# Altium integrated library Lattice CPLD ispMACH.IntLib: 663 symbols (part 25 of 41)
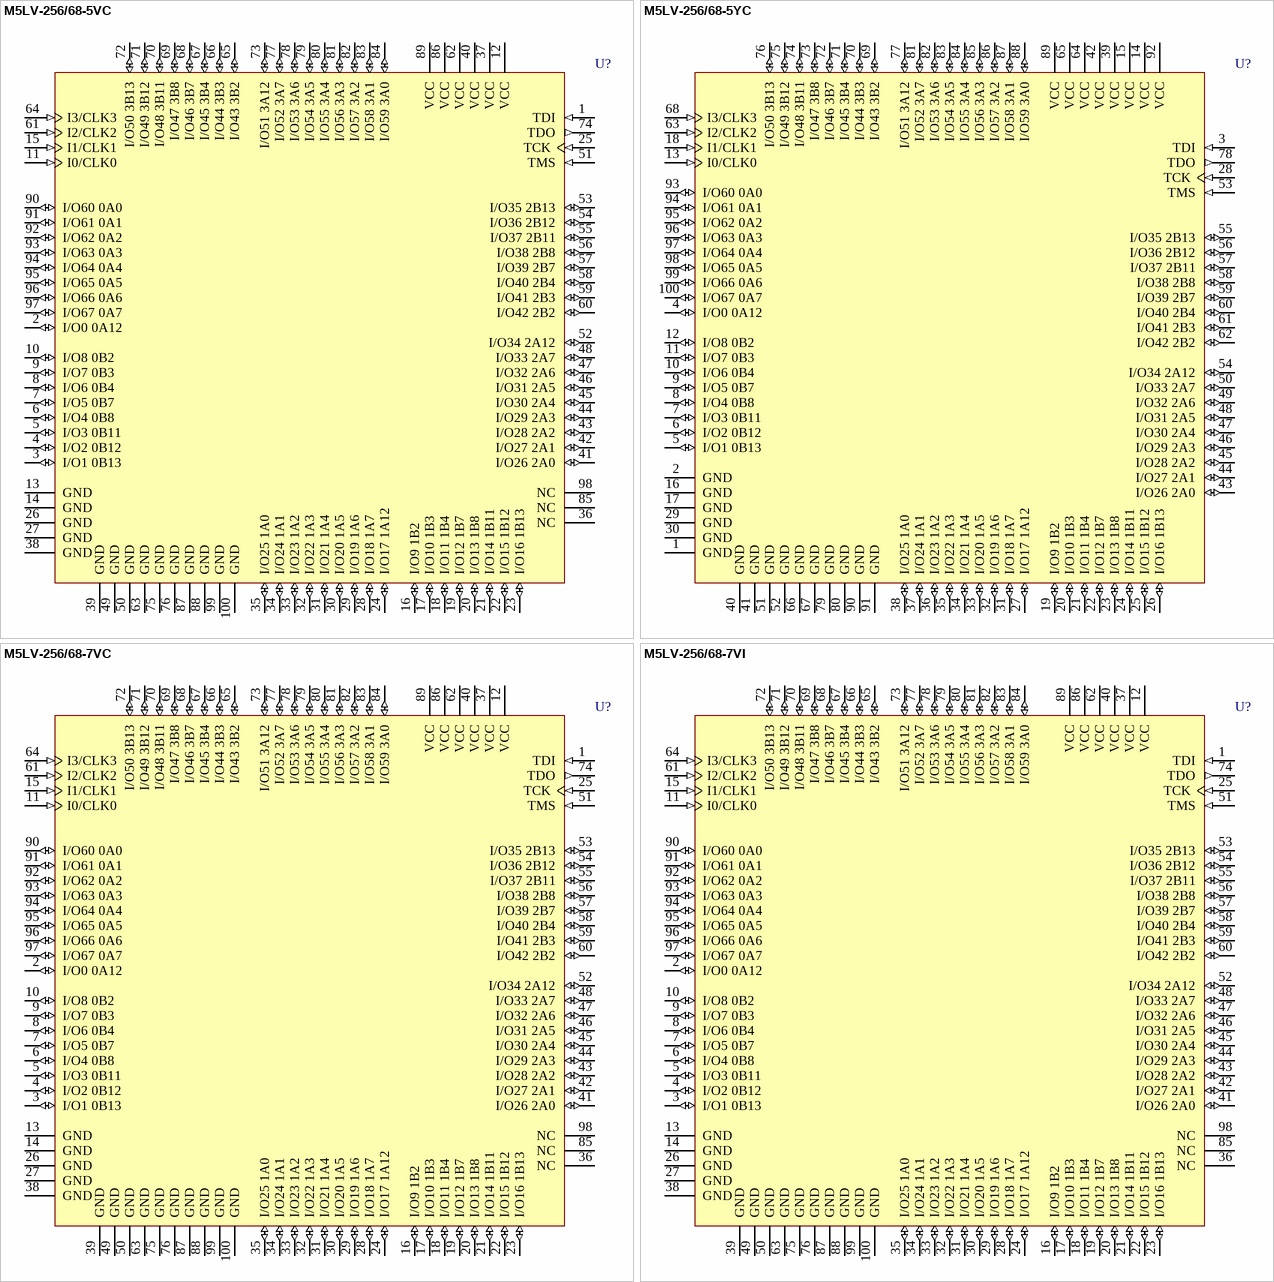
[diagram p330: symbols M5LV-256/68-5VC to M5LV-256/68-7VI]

## M5LV-256/68-7VI
designator U?
High-Density and High-I/O Complex PLD
footprint TQFP100_N (Thin QFP, 100-Leads, Body 14x14mm, Pitch 0.5mm, IPC Medium Density)
footprint TQFP100_L (Thin QFP, 100-Leads, Body 14x14mm, Pitch 0.5mm, IPC High Density)
footprint TQFP100_M (Thin QFP, 100-Leads, Body 14x14mm, Pitch 0.5mm, IPC Low Density)
3D model M5LV-TQFP100 (100-Pin Thin Quad Flat Pack (TQFP100))
pins: 1 TDI (in), 2 I/O0 0A12 (io), 3 I/O1 0B13 (io), 4 I/O2 0B12 (io), 5 I/O3 0B11 (io), 6 I/O4 0B8 (io), 7 I/O5 0B7 (io), 8 I/O6 0B4 (io), 9 I/O7 0B3 (io), 10 I/O8 0B2 (io), 11 I0/CLK0 (in), 12 VCC (power), 13 GND (power), 14 GND (power), 15 I1/CLK1 (in), 16 I/O9 1B2 (io), 17 I/O10 1B3 (io), 18 I/O11 1B4 (io), 19 I/O12 1B7 (io), 20 I/O13 1B8 (io), 21 I/O14 1B11 (io), 22 I/O15 1B12 (io), 23 I/O16 1B13 (io), 24 I/O17 1A12 (io), 25 TCK (in), 26 GND (power), 27 GND (power), 28 I/O18 1A7 (io), 29 I/O19 1A6 (io), 30 I/O20 1A5 (io), 31 I/O21 1A4 (io), 32 I/O22 1A3 (io), 33 I/O23 1A2 (io), 34 I/O24 1A1 (io), 35 I/O25 1A0 (io), 36 NC, 37 VCC (power), 38 GND (power), 39 GND (power), 40 VCC (power), 41 I/O26 2A0 (io), 42 I/O27 2A1 (io), 43 I/O28 2A2 (io), 44 I/O29 2A3 (io), 45 I/O30 2A4 (io), 46 I/O31 2A5 (io), 47 I/O32 2A6 (io), 48 I/O33 2A7 (io), 49 GND (power), 50 GND (power), 51 TMS (in), 52 I/O34 2A12 (io), 53 I/O35 2B13 (io), 54 I/O36 2B12 (io), 55 I/O37 2B11 (io), 56 I/O38 2B8 (io), 57 I/O39 2B7 (io), 58 I/O40 2B4 (io), 59 I/O41 2B3 (io), 60 I/O42 2B2 (io), 61 I2/CLK2 (in), 62 VCC (power), 63 GND (power), 64 I3/CLK3 (in), 65 I/O43 3B2 (io), 66 I/O44 3B3 (io), 67 I/O45 3B4 (io), 68 I/O46 3B7 (io), 69 I/O47 3B8 (io), 70 I/O48 3B11 (io), 71 I/O49 3B12 (io), 72 I/O50 3B13 (io), 73 I/O51 3A12 (io), 74 TDO (out), 75 GND (power), 76 GND (power), 77 I/O52 3A7 (io), 78 I/O53 3A6 (io), 79 I/O54 3A5 (io), 80 I/O55 3A4 (io), 81 I/O56 3A3 (io), 82 I/O57 3A2 (io), 83 I/O58 3A1 (io), 84 I/O59 3A0 (io), 85 NC, 86 VCC (power), 87 GND (power), 88 GND (power), 89 VCC (power), 90 I/O60 0A0 (io), 91 I/O61 0A1 (io), 92 I/O62 0A2 (io), 93 I/O63 0A3 (io), 94 I/O64 0A4 (io), 95 I/O65 0A5 (io), 96 I/O66 0A6 (io), 97 I/O67 0A7 (io), 98 NC, 99 GND (power), 100 GND (power)

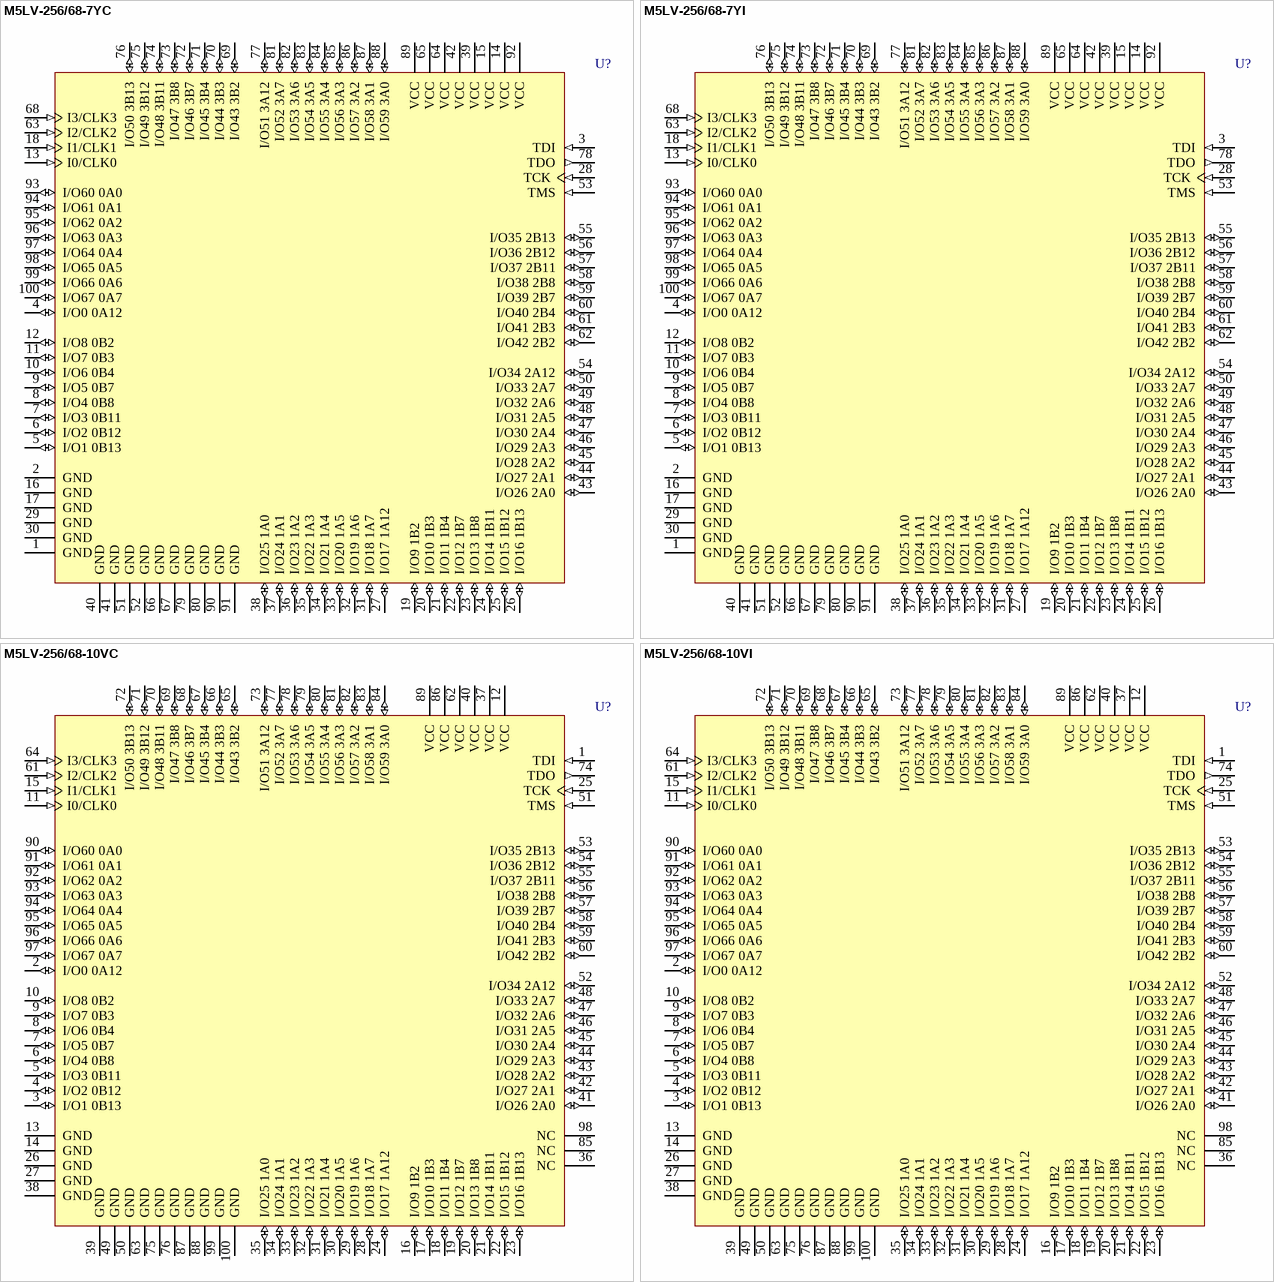
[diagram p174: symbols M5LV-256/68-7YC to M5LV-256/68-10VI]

## M5LV-256/68-7YC
designator U?
High-Density and High-I/O Complex PLD
footprint PQFP100_N (QFP, 100-Leads, Body 20x14mm, Pitch 0.65mm, IPC Medium Density)
footprint PQFP100_L (QFP, 100-Leads, Body 20x14mm, Pitch 0.65mm, IPC High Density)
footprint PQFP100_M (QFP, 100-Leads, Body 20x14mm, Pitch 0.65mm, IPC Low Density)
3D model PQFP-100 (100-Pin Quad Flat Pack Rectangular 0.65 mm Pitch)
pins: 1 GND (power), 2 GND (power), 3 TDI (in), 4 I/O0 0A12 (io), 5 I/O1 0B13 (io), 6 I/O2 0B12 (io), 7 I/O3 0B11 (io), 8 I/O4 0B8 (io), 9 I/O5 0B7 (io), 10 I/O6 0B4 (io), 11 I/O7 0B3 (io), 12 I/O8 0B2 (io), 13 I0/CLK0 (in), 14 VCC (power), 15 VCC (power), 16 GND (power), 17 GND (power), 18 I1/CLK1 (in), 19 I/O9 1B2 (io), 20 I/O10 1B3 (io), 21 I/O11 1B4 (io), 22 I/O12 1B7 (io), 23 I/O13 1B8 (io), 24 I/O14 1B11 (io), 25 I/O15 1B12 (io), 26 I/O16 1B13 (io), 27 I/O17 1A12 (io), 28 TCK (in), 29 GND (power), 30 GND (power), 31 I/O18 1A7 (io), 32 I/O19 1A6 (io), 33 I/O20 1A5 (io), 34 I/O21 1A4 (io), 35 I/O22 1A3 (io), 36 I/O23 1A2 (io), 37 I/O24 1A1 (io), 38 I/O25 1A0 (io), 39 VCC (power), 40 GND (power), 41 GND (power), 42 VCC (power), 43 I/O26 2A0 (io), 44 I/O27 2A1 (io), 45 I/O28 2A2 (io), 46 I/O29 2A3 (io), 47 I/O30 2A4 (io), 48 I/O31 2A5 (io), 49 I/O32 2A6 (io), 50 I/O33 2A7 (io), 51 GND (power), 52 GND (power), 53 TMS (in), 54 I/O34 2A12 (io), 55 I/O35 2B13 (io), 56 I/O36 2B12 (io), 57 I/O37 2B11 (io), 58 I/O38 2B8 (io), 59 I/O39 2B7 (io), 60 I/O40 2B4 (io), 61 I/O41 2B3 (io), 62 I/O42 2B2 (io), 63 I2/CLK2 (in), 64 VCC (power), 65 VCC (power), 66 GND (power), 67 GND (power), 68 I3/CLK3 (in), 69 I/O43 3B2 (io), 70 I/O44 3B3 (io), 71 I/O45 3B4 (io), 72 I/O46 3B7 (io), 73 I/O47 3B8 (io), 74 I/O48 3B11 (io), 75 I/O49 3B12 (io), 76 I/O50 3B13 (io), 77 I/O51 3A12 (io), 78 TDO (out), 79 GND (power), 80 GND (power), 81 I/O52 3A7 (io), 82 I/O53 3A6 (io), 83 I/O54 3A5 (io), 84 I/O55 3A4 (io), 85 I/O56 3A3 (io), 86 I/O57 3A2 (io), 87 I/O58 3A1 (io), 88 I/O59 3A0 (io), 89 VCC (power), 90 GND (power), 91 GND (power), 92 VCC (power), 93 I/O60 0A0 (io), 94 I/O61 0A1 (io), 95 I/O62 0A2 (io), 96 I/O63 0A3 (io), 97 I/O64 0A4 (io), 98 I/O65 0A5 (io), 99 I/O66 0A6 (io), 100 I/O67 0A7 (io)

## M5LV-256/68-7YI
designator U?
High-Density and High-I/O Complex PLD
footprint PQFP100_N (QFP, 100-Leads, Body 20x14mm, Pitch 0.65mm, IPC Medium Density)
footprint PQFP100_L (QFP, 100-Leads, Body 20x14mm, Pitch 0.65mm, IPC High Density)
footprint PQFP100_M (QFP, 100-Leads, Body 20x14mm, Pitch 0.65mm, IPC Low Density)
3D model PQFP-100 (100-Pin Quad Flat Pack Rectangular 0.65 mm Pitch)
pins: 1 GND (power), 2 GND (power), 3 TDI (in), 4 I/O0 0A12 (io), 5 I/O1 0B13 (io), 6 I/O2 0B12 (io), 7 I/O3 0B11 (io), 8 I/O4 0B8 (io), 9 I/O5 0B7 (io), 10 I/O6 0B4 (io), 11 I/O7 0B3 (io), 12 I/O8 0B2 (io), 13 I0/CLK0 (in), 14 VCC (power), 15 VCC (power), 16 GND (power), 17 GND (power), 18 I1/CLK1 (in), 19 I/O9 1B2 (io), 20 I/O10 1B3 (io), 21 I/O11 1B4 (io), 22 I/O12 1B7 (io), 23 I/O13 1B8 (io), 24 I/O14 1B11 (io), 25 I/O15 1B12 (io), 26 I/O16 1B13 (io), 27 I/O17 1A12 (io), 28 TCK (in), 29 GND (power), 30 GND (power), 31 I/O18 1A7 (io), 32 I/O19 1A6 (io), 33 I/O20 1A5 (io), 34 I/O21 1A4 (io), 35 I/O22 1A3 (io), 36 I/O23 1A2 (io), 37 I/O24 1A1 (io), 38 I/O25 1A0 (io), 39 VCC (power), 40 GND (power), 41 GND (power), 42 VCC (power), 43 I/O26 2A0 (io), 44 I/O27 2A1 (io), 45 I/O28 2A2 (io), 46 I/O29 2A3 (io), 47 I/O30 2A4 (io), 48 I/O31 2A5 (io), 49 I/O32 2A6 (io), 50 I/O33 2A7 (io), 51 GND (power), 52 GND (power), 53 TMS (in), 54 I/O34 2A12 (io), 55 I/O35 2B13 (io), 56 I/O36 2B12 (io), 57 I/O37 2B11 (io), 58 I/O38 2B8 (io), 59 I/O39 2B7 (io), 60 I/O40 2B4 (io), 61 I/O41 2B3 (io), 62 I/O42 2B2 (io), 63 I2/CLK2 (in), 64 VCC (power), 65 VCC (power), 66 GND (power), 67 GND (power), 68 I3/CLK3 (in), 69 I/O43 3B2 (io), 70 I/O44 3B3 (io), 71 I/O45 3B4 (io), 72 I/O46 3B7 (io), 73 I/O47 3B8 (io), 74 I/O48 3B11 (io), 75 I/O49 3B12 (io), 76 I/O50 3B13 (io), 77 I/O51 3A12 (io), 78 TDO (out), 79 GND (power), 80 GND (power), 81 I/O52 3A7 (io), 82 I/O53 3A6 (io), 83 I/O54 3A5 (io), 84 I/O55 3A4 (io), 85 I/O56 3A3 (io), 86 I/O57 3A2 (io), 87 I/O58 3A1 (io), 88 I/O59 3A0 (io), 89 VCC (power), 90 GND (power), 91 GND (power), 92 VCC (power), 93 I/O60 0A0 (io), 94 I/O61 0A1 (io), 95 I/O62 0A2 (io), 96 I/O63 0A3 (io), 97 I/O64 0A4 (io), 98 I/O65 0A5 (io), 99 I/O66 0A6 (io), 100 I/O67 0A7 (io)

## M5LV-256/68-10VC
designator U?
High-Density and High-I/O Complex PLD
footprint TQFP100_N (Thin QFP, 100-Leads, Body 14x14mm, Pitch 0.5mm, IPC Medium Density)
footprint TQFP100_L (Thin QFP, 100-Leads, Body 14x14mm, Pitch 0.5mm, IPC High Density)
footprint TQFP100_M (Thin QFP, 100-Leads, Body 14x14mm, Pitch 0.5mm, IPC Low Density)
3D model M5LV-TQFP100 (100-Pin Thin Quad Flat Pack (TQFP100))
pins: 1 TDI (in), 2 I/O0 0A12 (io), 3 I/O1 0B13 (io), 4 I/O2 0B12 (io), 5 I/O3 0B11 (io), 6 I/O4 0B8 (io), 7 I/O5 0B7 (io), 8 I/O6 0B4 (io), 9 I/O7 0B3 (io), 10 I/O8 0B2 (io), 11 I0/CLK0 (in), 12 VCC (power), 13 GND (power), 14 GND (power), 15 I1/CLK1 (in), 16 I/O9 1B2 (io), 17 I/O10 1B3 (io), 18 I/O11 1B4 (io), 19 I/O12 1B7 (io), 20 I/O13 1B8 (io), 21 I/O14 1B11 (io), 22 I/O15 1B12 (io), 23 I/O16 1B13 (io), 24 I/O17 1A12 (io), 25 TCK (in), 26 GND (power), 27 GND (power), 28 I/O18 1A7 (io), 29 I/O19 1A6 (io), 30 I/O20 1A5 (io), 31 I/O21 1A4 (io), 32 I/O22 1A3 (io), 33 I/O23 1A2 (io), 34 I/O24 1A1 (io), 35 I/O25 1A0 (io), 36 NC, 37 VCC (power), 38 GND (power), 39 GND (power), 40 VCC (power), 41 I/O26 2A0 (io), 42 I/O27 2A1 (io), 43 I/O28 2A2 (io), 44 I/O29 2A3 (io), 45 I/O30 2A4 (io), 46 I/O31 2A5 (io), 47 I/O32 2A6 (io), 48 I/O33 2A7 (io), 49 GND (power), 50 GND (power), 51 TMS (in), 52 I/O34 2A12 (io), 53 I/O35 2B13 (io), 54 I/O36 2B12 (io), 55 I/O37 2B11 (io), 56 I/O38 2B8 (io), 57 I/O39 2B7 (io), 58 I/O40 2B4 (io), 59 I/O41 2B3 (io), 60 I/O42 2B2 (io), 61 I2/CLK2 (in), 62 VCC (power), 63 GND (power), 64 I3/CLK3 (in), 65 I/O43 3B2 (io), 66 I/O44 3B3 (io), 67 I/O45 3B4 (io), 68 I/O46 3B7 (io), 69 I/O47 3B8 (io), 70 I/O48 3B11 (io), 71 I/O49 3B12 (io), 72 I/O50 3B13 (io), 73 I/O51 3A12 (io), 74 TDO (out), 75 GND (power), 76 GND (power), 77 I/O52 3A7 (io), 78 I/O53 3A6 (io), 79 I/O54 3A5 (io), 80 I/O55 3A4 (io), 81 I/O56 3A3 (io), 82 I/O57 3A2 (io), 83 I/O58 3A1 (io), 84 I/O59 3A0 (io), 85 NC, 86 VCC (power), 87 GND (power), 88 GND (power), 89 VCC (power), 90 I/O60 0A0 (io), 91 I/O61 0A1 (io), 92 I/O62 0A2 (io), 93 I/O63 0A3 (io), 94 I/O64 0A4 (io), 95 I/O65 0A5 (io), 96 I/O66 0A6 (io), 97 I/O67 0A7 (io), 98 NC, 99 GND (power), 100 GND (power)

## M5LV-256/68-10VI
designator U?
High-Density and High-I/O Complex PLD
footprint TQFP100_N (Thin QFP, 100-Leads, Body 14x14mm, Pitch 0.5mm, IPC Medium Density)
footprint TQFP100_L (Thin QFP, 100-Leads, Body 14x14mm, Pitch 0.5mm, IPC High Density)
footprint TQFP100_M (Thin QFP, 100-Leads, Body 14x14mm, Pitch 0.5mm, IPC Low Density)
3D model M5LV-TQFP100 (100-Pin Thin Quad Flat Pack (TQFP100))
pins: 1 TDI (in), 2 I/O0 0A12 (io), 3 I/O1 0B13 (io), 4 I/O2 0B12 (io), 5 I/O3 0B11 (io), 6 I/O4 0B8 (io), 7 I/O5 0B7 (io), 8 I/O6 0B4 (io), 9 I/O7 0B3 (io), 10 I/O8 0B2 (io), 11 I0/CLK0 (in), 12 VCC (power), 13 GND (power), 14 GND (power), 15 I1/CLK1 (in), 16 I/O9 1B2 (io), 17 I/O10 1B3 (io), 18 I/O11 1B4 (io), 19 I/O12 1B7 (io), 20 I/O13 1B8 (io), 21 I/O14 1B11 (io), 22 I/O15 1B12 (io), 23 I/O16 1B13 (io), 24 I/O17 1A12 (io), 25 TCK (in), 26 GND (power), 27 GND (power), 28 I/O18 1A7 (io), 29 I/O19 1A6 (io), 30 I/O20 1A5 (io), 31 I/O21 1A4 (io), 32 I/O22 1A3 (io), 33 I/O23 1A2 (io), 34 I/O24 1A1 (io), 35 I/O25 1A0 (io), 36 NC, 37 VCC (power), 38 GND (power), 39 GND (power), 40 VCC (power), 41 I/O26 2A0 (io), 42 I/O27 2A1 (io), 43 I/O28 2A2 (io), 44 I/O29 2A3 (io), 45 I/O30 2A4 (io), 46 I/O31 2A5 (io), 47 I/O32 2A6 (io), 48 I/O33 2A7 (io), 49 GND (power), 50 GND (power), 51 TMS (in), 52 I/O34 2A12 (io), 53 I/O35 2B13 (io), 54 I/O36 2B12 (io), 55 I/O37 2B11 (io), 56 I/O38 2B8 (io), 57 I/O39 2B7 (io), 58 I/O40 2B4 (io), 59 I/O41 2B3 (io), 60 I/O42 2B2 (io), 61 I2/CLK2 (in), 62 VCC (power), 63 GND (power), 64 I3/CLK3 (in), 65 I/O43 3B2 (io), 66 I/O44 3B3 (io), 67 I/O45 3B4 (io), 68 I/O46 3B7 (io), 69 I/O47 3B8 (io), 70 I/O48 3B11 (io), 71 I/O49 3B12 (io), 72 I/O50 3B13 (io), 73 I/O51 3A12 (io), 74 TDO (out), 75 GND (power), 76 GND (power), 77 I/O52 3A7 (io), 78 I/O53 3A6 (io), 79 I/O54 3A5 (io), 80 I/O55 3A4 (io), 81 I/O56 3A3 (io), 82 I/O57 3A2 (io), 83 I/O58 3A1 (io), 84 I/O59 3A0 (io), 85 NC, 86 VCC (power), 87 GND (power), 88 GND (power), 89 VCC (power), 90 I/O60 0A0 (io), 91 I/O61 0A1 (io), 92 I/O62 0A2 (io), 93 I/O63 0A3 (io), 94 I/O64 0A4 (io), 95 I/O65 0A5 (io), 96 I/O66 0A6 (io), 97 I/O67 0A7 (io), 98 NC, 99 GND (power), 100 GND (power)

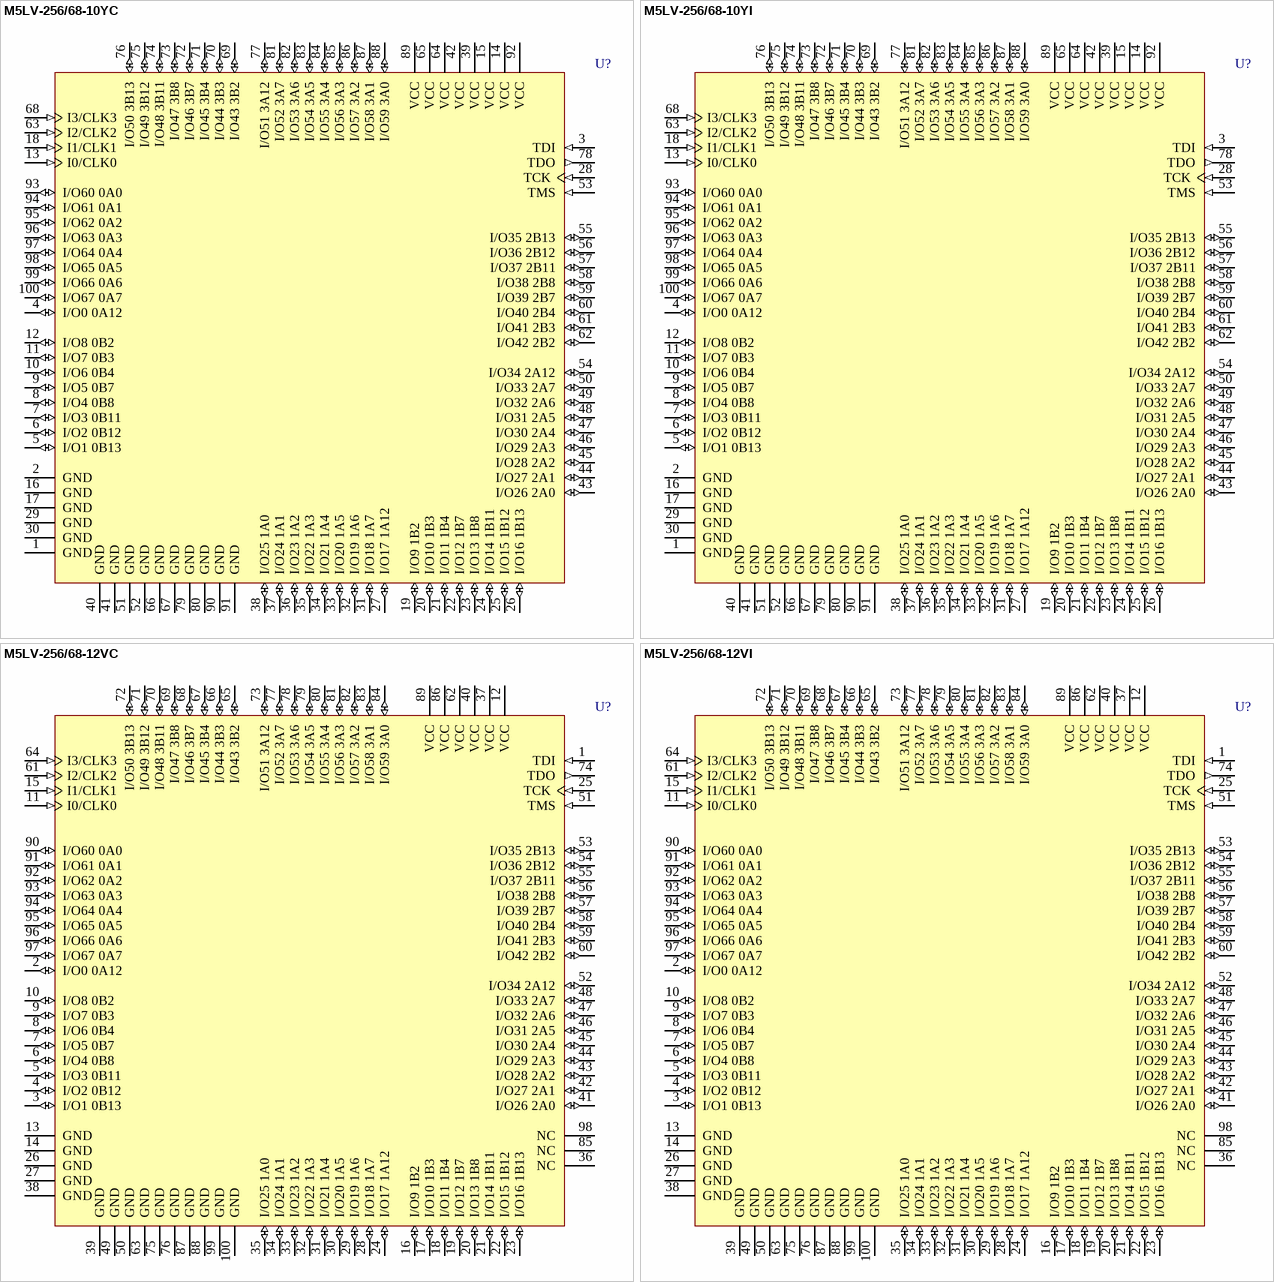
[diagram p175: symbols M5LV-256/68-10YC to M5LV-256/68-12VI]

## M5LV-256/68-10YC
designator U?
High-Density and High-I/O Complex PLD
footprint PQFP100_N (QFP, 100-Leads, Body 20x14mm, Pitch 0.65mm, IPC Medium Density)
footprint PQFP100_L (QFP, 100-Leads, Body 20x14mm, Pitch 0.65mm, IPC High Density)
footprint PQFP100_M (QFP, 100-Leads, Body 20x14mm, Pitch 0.65mm, IPC Low Density)
3D model PQFP-100 (100-Pin Quad Flat Pack Rectangular 0.65 mm Pitch)
pins: 1 GND (power), 2 GND (power), 3 TDI (in), 4 I/O0 0A12 (io), 5 I/O1 0B13 (io), 6 I/O2 0B12 (io), 7 I/O3 0B11 (io), 8 I/O4 0B8 (io), 9 I/O5 0B7 (io), 10 I/O6 0B4 (io), 11 I/O7 0B3 (io), 12 I/O8 0B2 (io), 13 I0/CLK0 (in), 14 VCC (power), 15 VCC (power), 16 GND (power), 17 GND (power), 18 I1/CLK1 (in), 19 I/O9 1B2 (io), 20 I/O10 1B3 (io), 21 I/O11 1B4 (io), 22 I/O12 1B7 (io), 23 I/O13 1B8 (io), 24 I/O14 1B11 (io), 25 I/O15 1B12 (io), 26 I/O16 1B13 (io), 27 I/O17 1A12 (io), 28 TCK (in), 29 GND (power), 30 GND (power), 31 I/O18 1A7 (io), 32 I/O19 1A6 (io), 33 I/O20 1A5 (io), 34 I/O21 1A4 (io), 35 I/O22 1A3 (io), 36 I/O23 1A2 (io), 37 I/O24 1A1 (io), 38 I/O25 1A0 (io), 39 VCC (power), 40 GND (power), 41 GND (power), 42 VCC (power), 43 I/O26 2A0 (io), 44 I/O27 2A1 (io), 45 I/O28 2A2 (io), 46 I/O29 2A3 (io), 47 I/O30 2A4 (io), 48 I/O31 2A5 (io), 49 I/O32 2A6 (io), 50 I/O33 2A7 (io), 51 GND (power), 52 GND (power), 53 TMS (in), 54 I/O34 2A12 (io), 55 I/O35 2B13 (io), 56 I/O36 2B12 (io), 57 I/O37 2B11 (io), 58 I/O38 2B8 (io), 59 I/O39 2B7 (io), 60 I/O40 2B4 (io), 61 I/O41 2B3 (io), 62 I/O42 2B2 (io), 63 I2/CLK2 (in), 64 VCC (power), 65 VCC (power), 66 GND (power), 67 GND (power), 68 I3/CLK3 (in), 69 I/O43 3B2 (io), 70 I/O44 3B3 (io), 71 I/O45 3B4 (io), 72 I/O46 3B7 (io), 73 I/O47 3B8 (io), 74 I/O48 3B11 (io), 75 I/O49 3B12 (io), 76 I/O50 3B13 (io), 77 I/O51 3A12 (io), 78 TDO (out), 79 GND (power), 80 GND (power), 81 I/O52 3A7 (io), 82 I/O53 3A6 (io), 83 I/O54 3A5 (io), 84 I/O55 3A4 (io), 85 I/O56 3A3 (io), 86 I/O57 3A2 (io), 87 I/O58 3A1 (io), 88 I/O59 3A0 (io), 89 VCC (power), 90 GND (power), 91 GND (power), 92 VCC (power), 93 I/O60 0A0 (io), 94 I/O61 0A1 (io), 95 I/O62 0A2 (io), 96 I/O63 0A3 (io), 97 I/O64 0A4 (io), 98 I/O65 0A5 (io), 99 I/O66 0A6 (io), 100 I/O67 0A7 (io)

## M5LV-256/68-10YI
designator U?
High-Density and High-I/O Complex PLD
footprint PQFP100_N (QFP, 100-Leads, Body 20x14mm, Pitch 0.65mm, IPC Medium Density)
footprint PQFP100_L (QFP, 100-Leads, Body 20x14mm, Pitch 0.65mm, IPC High Density)
footprint PQFP100_M (QFP, 100-Leads, Body 20x14mm, Pitch 0.65mm, IPC Low Density)
3D model PQFP-100 (100-Pin Quad Flat Pack Rectangular 0.65 mm Pitch)
pins: 1 GND (power), 2 GND (power), 3 TDI (in), 4 I/O0 0A12 (io), 5 I/O1 0B13 (io), 6 I/O2 0B12 (io), 7 I/O3 0B11 (io), 8 I/O4 0B8 (io), 9 I/O5 0B7 (io), 10 I/O6 0B4 (io), 11 I/O7 0B3 (io), 12 I/O8 0B2 (io), 13 I0/CLK0 (in), 14 VCC (power), 15 VCC (power), 16 GND (power), 17 GND (power), 18 I1/CLK1 (in), 19 I/O9 1B2 (io), 20 I/O10 1B3 (io), 21 I/O11 1B4 (io), 22 I/O12 1B7 (io), 23 I/O13 1B8 (io), 24 I/O14 1B11 (io), 25 I/O15 1B12 (io), 26 I/O16 1B13 (io), 27 I/O17 1A12 (io), 28 TCK (in), 29 GND (power), 30 GND (power), 31 I/O18 1A7 (io), 32 I/O19 1A6 (io), 33 I/O20 1A5 (io), 34 I/O21 1A4 (io), 35 I/O22 1A3 (io), 36 I/O23 1A2 (io), 37 I/O24 1A1 (io), 38 I/O25 1A0 (io), 39 VCC (power), 40 GND (power), 41 GND (power), 42 VCC (power), 43 I/O26 2A0 (io), 44 I/O27 2A1 (io), 45 I/O28 2A2 (io), 46 I/O29 2A3 (io), 47 I/O30 2A4 (io), 48 I/O31 2A5 (io), 49 I/O32 2A6 (io), 50 I/O33 2A7 (io), 51 GND (power), 52 GND (power), 53 TMS (in), 54 I/O34 2A12 (io), 55 I/O35 2B13 (io), 56 I/O36 2B12 (io), 57 I/O37 2B11 (io), 58 I/O38 2B8 (io), 59 I/O39 2B7 (io), 60 I/O40 2B4 (io), 61 I/O41 2B3 (io), 62 I/O42 2B2 (io), 63 I2/CLK2 (in), 64 VCC (power), 65 VCC (power), 66 GND (power), 67 GND (power), 68 I3/CLK3 (in), 69 I/O43 3B2 (io), 70 I/O44 3B3 (io), 71 I/O45 3B4 (io), 72 I/O46 3B7 (io), 73 I/O47 3B8 (io), 74 I/O48 3B11 (io), 75 I/O49 3B12 (io), 76 I/O50 3B13 (io), 77 I/O51 3A12 (io), 78 TDO (out), 79 GND (power), 80 GND (power), 81 I/O52 3A7 (io), 82 I/O53 3A6 (io), 83 I/O54 3A5 (io), 84 I/O55 3A4 (io), 85 I/O56 3A3 (io), 86 I/O57 3A2 (io), 87 I/O58 3A1 (io), 88 I/O59 3A0 (io), 89 VCC (power), 90 GND (power), 91 GND (power), 92 VCC (power), 93 I/O60 0A0 (io), 94 I/O61 0A1 (io), 95 I/O62 0A2 (io), 96 I/O63 0A3 (io), 97 I/O64 0A4 (io), 98 I/O65 0A5 (io), 99 I/O66 0A6 (io), 100 I/O67 0A7 (io)

## M5LV-256/68-12VC
designator U?
High-Density and High-I/O Complex PLD
footprint TQFP100_N (Thin QFP, 100-Leads, Body 14x14mm, Pitch 0.5mm, IPC Medium Density)
footprint TQFP100_L (Thin QFP, 100-Leads, Body 14x14mm, Pitch 0.5mm, IPC High Density)
footprint TQFP100_M (Thin QFP, 100-Leads, Body 14x14mm, Pitch 0.5mm, IPC Low Density)
3D model M5LV-TQFP100 (100-Pin Thin Quad Flat Pack (TQFP100))
pins: 1 TDI (in), 2 I/O0 0A12 (io), 3 I/O1 0B13 (io), 4 I/O2 0B12 (io), 5 I/O3 0B11 (io), 6 I/O4 0B8 (io), 7 I/O5 0B7 (io), 8 I/O6 0B4 (io), 9 I/O7 0B3 (io), 10 I/O8 0B2 (io), 11 I0/CLK0 (in), 12 VCC (power), 13 GND (power), 14 GND (power), 15 I1/CLK1 (in), 16 I/O9 1B2 (io), 17 I/O10 1B3 (io), 18 I/O11 1B4 (io), 19 I/O12 1B7 (io), 20 I/O13 1B8 (io), 21 I/O14 1B11 (io), 22 I/O15 1B12 (io), 23 I/O16 1B13 (io), 24 I/O17 1A12 (io), 25 TCK (in), 26 GND (power), 27 GND (power), 28 I/O18 1A7 (io), 29 I/O19 1A6 (io), 30 I/O20 1A5 (io), 31 I/O21 1A4 (io), 32 I/O22 1A3 (io), 33 I/O23 1A2 (io), 34 I/O24 1A1 (io), 35 I/O25 1A0 (io), 36 NC, 37 VCC (power), 38 GND (power), 39 GND (power), 40 VCC (power), 41 I/O26 2A0 (io), 42 I/O27 2A1 (io), 43 I/O28 2A2 (io), 44 I/O29 2A3 (io), 45 I/O30 2A4 (io), 46 I/O31 2A5 (io), 47 I/O32 2A6 (io), 48 I/O33 2A7 (io), 49 GND (power), 50 GND (power), 51 TMS (in), 52 I/O34 2A12 (io), 53 I/O35 2B13 (io), 54 I/O36 2B12 (io), 55 I/O37 2B11 (io), 56 I/O38 2B8 (io), 57 I/O39 2B7 (io), 58 I/O40 2B4 (io), 59 I/O41 2B3 (io), 60 I/O42 2B2 (io), 61 I2/CLK2 (in), 62 VCC (power), 63 GND (power), 64 I3/CLK3 (in), 65 I/O43 3B2 (io), 66 I/O44 3B3 (io), 67 I/O45 3B4 (io), 68 I/O46 3B7 (io), 69 I/O47 3B8 (io), 70 I/O48 3B11 (io), 71 I/O49 3B12 (io), 72 I/O50 3B13 (io), 73 I/O51 3A12 (io), 74 TDO (out), 75 GND (power), 76 GND (power), 77 I/O52 3A7 (io), 78 I/O53 3A6 (io), 79 I/O54 3A5 (io), 80 I/O55 3A4 (io), 81 I/O56 3A3 (io), 82 I/O57 3A2 (io), 83 I/O58 3A1 (io), 84 I/O59 3A0 (io), 85 NC, 86 VCC (power), 87 GND (power), 88 GND (power), 89 VCC (power), 90 I/O60 0A0 (io), 91 I/O61 0A1 (io), 92 I/O62 0A2 (io), 93 I/O63 0A3 (io), 94 I/O64 0A4 (io), 95 I/O65 0A5 (io), 96 I/O66 0A6 (io), 97 I/O67 0A7 (io), 98 NC, 99 GND (power), 100 GND (power)

## M5LV-256/68-12VI
designator U?
High-Density and High-I/O Complex PLD
footprint TQFP100_N (Thin QFP, 100-Leads, Body 14x14mm, Pitch 0.5mm, IPC Medium Density)
footprint TQFP100_L (Thin QFP, 100-Leads, Body 14x14mm, Pitch 0.5mm, IPC High Density)
footprint TQFP100_M (Thin QFP, 100-Leads, Body 14x14mm, Pitch 0.5mm, IPC Low Density)
3D model M5LV-TQFP100 (100-Pin Thin Quad Flat Pack (TQFP100))
pins: 1 TDI (in), 2 I/O0 0A12 (io), 3 I/O1 0B13 (io), 4 I/O2 0B12 (io), 5 I/O3 0B11 (io), 6 I/O4 0B8 (io), 7 I/O5 0B7 (io), 8 I/O6 0B4 (io), 9 I/O7 0B3 (io), 10 I/O8 0B2 (io), 11 I0/CLK0 (in), 12 VCC (power), 13 GND (power), 14 GND (power), 15 I1/CLK1 (in), 16 I/O9 1B2 (io), 17 I/O10 1B3 (io), 18 I/O11 1B4 (io), 19 I/O12 1B7 (io), 20 I/O13 1B8 (io), 21 I/O14 1B11 (io), 22 I/O15 1B12 (io), 23 I/O16 1B13 (io), 24 I/O17 1A12 (io), 25 TCK (in), 26 GND (power), 27 GND (power), 28 I/O18 1A7 (io), 29 I/O19 1A6 (io), 30 I/O20 1A5 (io), 31 I/O21 1A4 (io), 32 I/O22 1A3 (io), 33 I/O23 1A2 (io), 34 I/O24 1A1 (io), 35 I/O25 1A0 (io), 36 NC, 37 VCC (power), 38 GND (power), 39 GND (power), 40 VCC (power), 41 I/O26 2A0 (io), 42 I/O27 2A1 (io), 43 I/O28 2A2 (io), 44 I/O29 2A3 (io), 45 I/O30 2A4 (io), 46 I/O31 2A5 (io), 47 I/O32 2A6 (io), 48 I/O33 2A7 (io), 49 GND (power), 50 GND (power), 51 TMS (in), 52 I/O34 2A12 (io), 53 I/O35 2B13 (io), 54 I/O36 2B12 (io), 55 I/O37 2B11 (io), 56 I/O38 2B8 (io), 57 I/O39 2B7 (io), 58 I/O40 2B4 (io), 59 I/O41 2B3 (io), 60 I/O42 2B2 (io), 61 I2/CLK2 (in), 62 VCC (power), 63 GND (power), 64 I3/CLK3 (in), 65 I/O43 3B2 (io), 66 I/O44 3B3 (io), 67 I/O45 3B4 (io), 68 I/O46 3B7 (io), 69 I/O47 3B8 (io), 70 I/O48 3B11 (io), 71 I/O49 3B12 (io), 72 I/O50 3B13 (io), 73 I/O51 3A12 (io), 74 TDO (out), 75 GND (power), 76 GND (power), 77 I/O52 3A7 (io), 78 I/O53 3A6 (io), 79 I/O54 3A5 (io), 80 I/O55 3A4 (io), 81 I/O56 3A3 (io), 82 I/O57 3A2 (io), 83 I/O58 3A1 (io), 84 I/O59 3A0 (io), 85 NC, 86 VCC (power), 87 GND (power), 88 GND (power), 89 VCC (power), 90 I/O60 0A0 (io), 91 I/O61 0A1 (io), 92 I/O62 0A2 (io), 93 I/O63 0A3 (io), 94 I/O64 0A4 (io), 95 I/O65 0A5 (io), 96 I/O66 0A6 (io), 97 I/O67 0A7 (io), 98 NC, 99 GND (power), 100 GND (power)

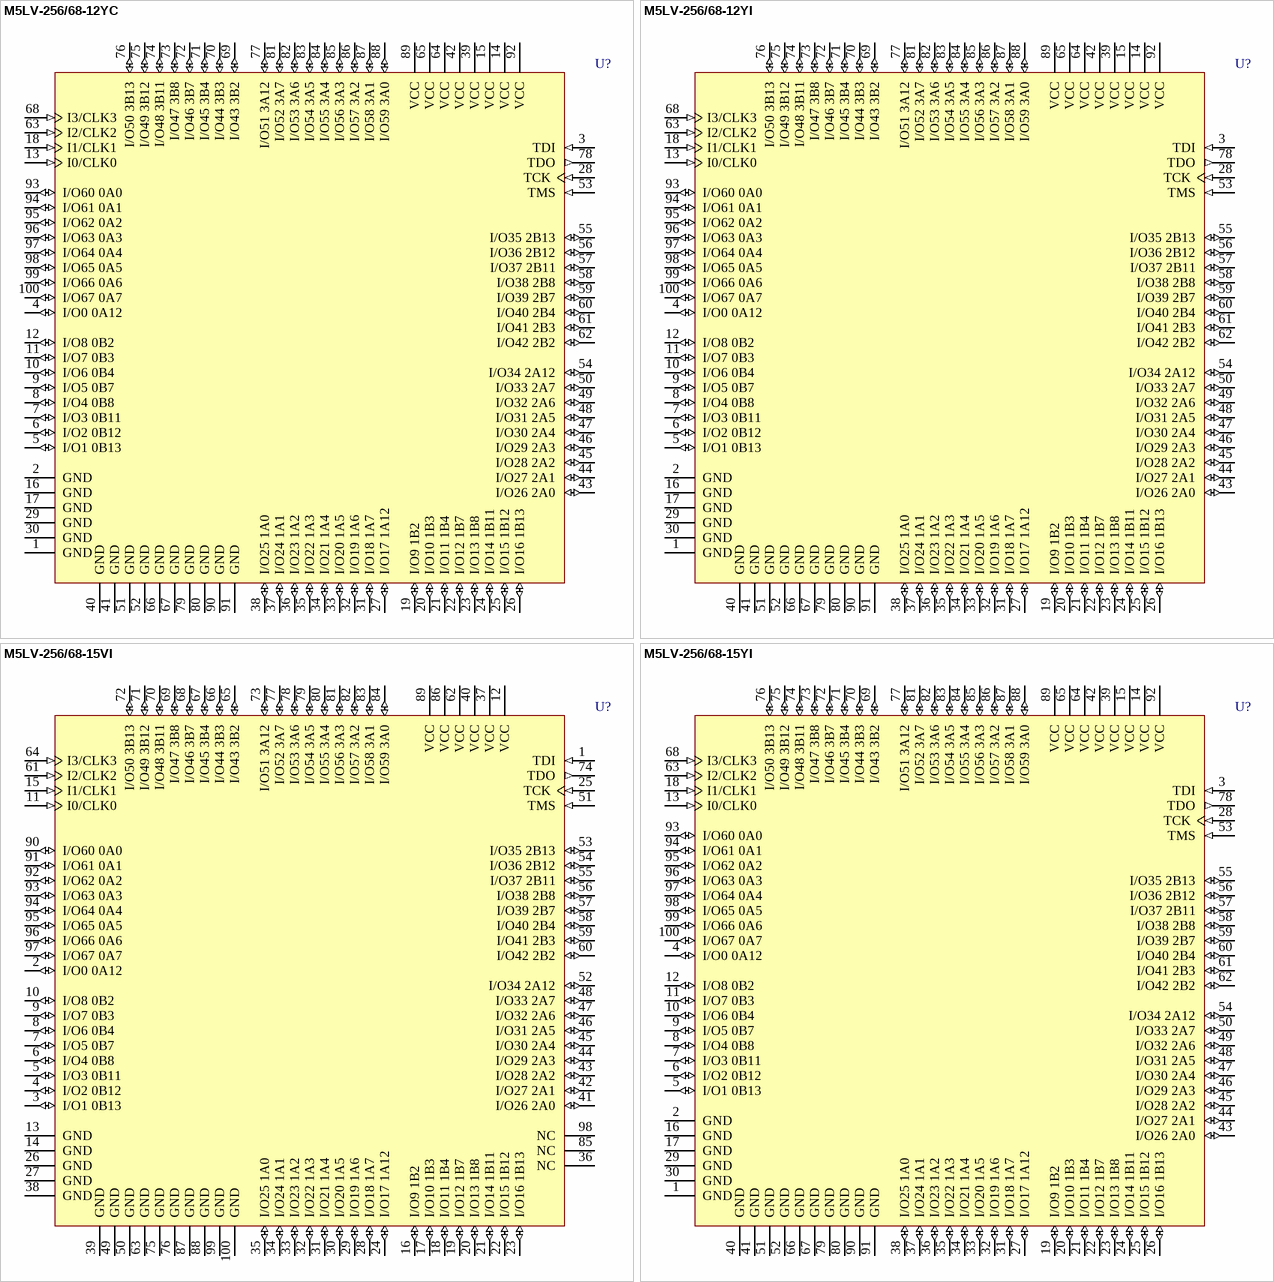
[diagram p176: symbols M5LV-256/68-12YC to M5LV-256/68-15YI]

## M5LV-256/68-12YC
designator U?
High-Density and High-I/O Complex PLD
footprint PQFP100_N (QFP, 100-Leads, Body 20x14mm, Pitch 0.65mm, IPC Medium Density)
footprint PQFP100_L (QFP, 100-Leads, Body 20x14mm, Pitch 0.65mm, IPC High Density)
footprint PQFP100_M (QFP, 100-Leads, Body 20x14mm, Pitch 0.65mm, IPC Low Density)
3D model PQFP-100 (100-Pin Quad Flat Pack Rectangular 0.65 mm Pitch)
pins: 1 GND (power), 2 GND (power), 3 TDI (in), 4 I/O0 0A12 (io), 5 I/O1 0B13 (io), 6 I/O2 0B12 (io), 7 I/O3 0B11 (io), 8 I/O4 0B8 (io), 9 I/O5 0B7 (io), 10 I/O6 0B4 (io), 11 I/O7 0B3 (io), 12 I/O8 0B2 (io), 13 I0/CLK0 (in), 14 VCC (power), 15 VCC (power), 16 GND (power), 17 GND (power), 18 I1/CLK1 (in), 19 I/O9 1B2 (io), 20 I/O10 1B3 (io), 21 I/O11 1B4 (io), 22 I/O12 1B7 (io), 23 I/O13 1B8 (io), 24 I/O14 1B11 (io), 25 I/O15 1B12 (io), 26 I/O16 1B13 (io), 27 I/O17 1A12 (io), 28 TCK (in), 29 GND (power), 30 GND (power), 31 I/O18 1A7 (io), 32 I/O19 1A6 (io), 33 I/O20 1A5 (io), 34 I/O21 1A4 (io), 35 I/O22 1A3 (io), 36 I/O23 1A2 (io), 37 I/O24 1A1 (io), 38 I/O25 1A0 (io), 39 VCC (power), 40 GND (power), 41 GND (power), 42 VCC (power), 43 I/O26 2A0 (io), 44 I/O27 2A1 (io), 45 I/O28 2A2 (io), 46 I/O29 2A3 (io), 47 I/O30 2A4 (io), 48 I/O31 2A5 (io), 49 I/O32 2A6 (io), 50 I/O33 2A7 (io), 51 GND (power), 52 GND (power), 53 TMS (in), 54 I/O34 2A12 (io), 55 I/O35 2B13 (io), 56 I/O36 2B12 (io), 57 I/O37 2B11 (io), 58 I/O38 2B8 (io), 59 I/O39 2B7 (io), 60 I/O40 2B4 (io), 61 I/O41 2B3 (io), 62 I/O42 2B2 (io), 63 I2/CLK2 (in), 64 VCC (power), 65 VCC (power), 66 GND (power), 67 GND (power), 68 I3/CLK3 (in), 69 I/O43 3B2 (io), 70 I/O44 3B3 (io), 71 I/O45 3B4 (io), 72 I/O46 3B7 (io), 73 I/O47 3B8 (io), 74 I/O48 3B11 (io), 75 I/O49 3B12 (io), 76 I/O50 3B13 (io), 77 I/O51 3A12 (io), 78 TDO (out), 79 GND (power), 80 GND (power), 81 I/O52 3A7 (io), 82 I/O53 3A6 (io), 83 I/O54 3A5 (io), 84 I/O55 3A4 (io), 85 I/O56 3A3 (io), 86 I/O57 3A2 (io), 87 I/O58 3A1 (io), 88 I/O59 3A0 (io), 89 VCC (power), 90 GND (power), 91 GND (power), 92 VCC (power), 93 I/O60 0A0 (io), 94 I/O61 0A1 (io), 95 I/O62 0A2 (io), 96 I/O63 0A3 (io), 97 I/O64 0A4 (io), 98 I/O65 0A5 (io), 99 I/O66 0A6 (io), 100 I/O67 0A7 (io)

## M5LV-256/68-12YI
designator U?
High-Density and High-I/O Complex PLD
footprint PQFP100_N (QFP, 100-Leads, Body 20x14mm, Pitch 0.65mm, IPC Medium Density)
footprint PQFP100_L (QFP, 100-Leads, Body 20x14mm, Pitch 0.65mm, IPC High Density)
footprint PQFP100_M (QFP, 100-Leads, Body 20x14mm, Pitch 0.65mm, IPC Low Density)
3D model PQFP-100 (100-Pin Quad Flat Pack Rectangular 0.65 mm Pitch)
pins: 1 GND (power), 2 GND (power), 3 TDI (in), 4 I/O0 0A12 (io), 5 I/O1 0B13 (io), 6 I/O2 0B12 (io), 7 I/O3 0B11 (io), 8 I/O4 0B8 (io), 9 I/O5 0B7 (io), 10 I/O6 0B4 (io), 11 I/O7 0B3 (io), 12 I/O8 0B2 (io), 13 I0/CLK0 (in), 14 VCC (power), 15 VCC (power), 16 GND (power), 17 GND (power), 18 I1/CLK1 (in), 19 I/O9 1B2 (io), 20 I/O10 1B3 (io), 21 I/O11 1B4 (io), 22 I/O12 1B7 (io), 23 I/O13 1B8 (io), 24 I/O14 1B11 (io), 25 I/O15 1B12 (io), 26 I/O16 1B13 (io), 27 I/O17 1A12 (io), 28 TCK (in), 29 GND (power), 30 GND (power), 31 I/O18 1A7 (io), 32 I/O19 1A6 (io), 33 I/O20 1A5 (io), 34 I/O21 1A4 (io), 35 I/O22 1A3 (io), 36 I/O23 1A2 (io), 37 I/O24 1A1 (io), 38 I/O25 1A0 (io), 39 VCC (power), 40 GND (power), 41 GND (power), 42 VCC (power), 43 I/O26 2A0 (io), 44 I/O27 2A1 (io), 45 I/O28 2A2 (io), 46 I/O29 2A3 (io), 47 I/O30 2A4 (io), 48 I/O31 2A5 (io), 49 I/O32 2A6 (io), 50 I/O33 2A7 (io), 51 GND (power), 52 GND (power), 53 TMS (in), 54 I/O34 2A12 (io), 55 I/O35 2B13 (io), 56 I/O36 2B12 (io), 57 I/O37 2B11 (io), 58 I/O38 2B8 (io), 59 I/O39 2B7 (io), 60 I/O40 2B4 (io), 61 I/O41 2B3 (io), 62 I/O42 2B2 (io), 63 I2/CLK2 (in), 64 VCC (power), 65 VCC (power), 66 GND (power), 67 GND (power), 68 I3/CLK3 (in), 69 I/O43 3B2 (io), 70 I/O44 3B3 (io), 71 I/O45 3B4 (io), 72 I/O46 3B7 (io), 73 I/O47 3B8 (io), 74 I/O48 3B11 (io), 75 I/O49 3B12 (io), 76 I/O50 3B13 (io), 77 I/O51 3A12 (io), 78 TDO (out), 79 GND (power), 80 GND (power), 81 I/O52 3A7 (io), 82 I/O53 3A6 (io), 83 I/O54 3A5 (io), 84 I/O55 3A4 (io), 85 I/O56 3A3 (io), 86 I/O57 3A2 (io), 87 I/O58 3A1 (io), 88 I/O59 3A0 (io), 89 VCC (power), 90 GND (power), 91 GND (power), 92 VCC (power), 93 I/O60 0A0 (io), 94 I/O61 0A1 (io), 95 I/O62 0A2 (io), 96 I/O63 0A3 (io), 97 I/O64 0A4 (io), 98 I/O65 0A5 (io), 99 I/O66 0A6 (io), 100 I/O67 0A7 (io)

## M5LV-256/68-15VI
designator U?
High-Density and High-I/O Complex PLD
footprint TQFP100_N (Thin QFP, 100-Leads, Body 14x14mm, Pitch 0.5mm, IPC Medium Density)
footprint TQFP100_L (Thin QFP, 100-Leads, Body 14x14mm, Pitch 0.5mm, IPC High Density)
footprint TQFP100_M (Thin QFP, 100-Leads, Body 14x14mm, Pitch 0.5mm, IPC Low Density)
3D model M5LV-TQFP100 (100-Pin Thin Quad Flat Pack (TQFP100))
pins: 1 TDI (in), 2 I/O0 0A12 (io), 3 I/O1 0B13 (io), 4 I/O2 0B12 (io), 5 I/O3 0B11 (io), 6 I/O4 0B8 (io), 7 I/O5 0B7 (io), 8 I/O6 0B4 (io), 9 I/O7 0B3 (io), 10 I/O8 0B2 (io), 11 I0/CLK0 (in), 12 VCC (power), 13 GND (power), 14 GND (power), 15 I1/CLK1 (in), 16 I/O9 1B2 (io), 17 I/O10 1B3 (io), 18 I/O11 1B4 (io), 19 I/O12 1B7 (io), 20 I/O13 1B8 (io), 21 I/O14 1B11 (io), 22 I/O15 1B12 (io), 23 I/O16 1B13 (io), 24 I/O17 1A12 (io), 25 TCK (in), 26 GND (power), 27 GND (power), 28 I/O18 1A7 (io), 29 I/O19 1A6 (io), 30 I/O20 1A5 (io), 31 I/O21 1A4 (io), 32 I/O22 1A3 (io), 33 I/O23 1A2 (io), 34 I/O24 1A1 (io), 35 I/O25 1A0 (io), 36 NC, 37 VCC (power), 38 GND (power), 39 GND (power), 40 VCC (power), 41 I/O26 2A0 (io), 42 I/O27 2A1 (io), 43 I/O28 2A2 (io), 44 I/O29 2A3 (io), 45 I/O30 2A4 (io), 46 I/O31 2A5 (io), 47 I/O32 2A6 (io), 48 I/O33 2A7 (io), 49 GND (power), 50 GND (power), 51 TMS (in), 52 I/O34 2A12 (io), 53 I/O35 2B13 (io), 54 I/O36 2B12 (io), 55 I/O37 2B11 (io), 56 I/O38 2B8 (io), 57 I/O39 2B7 (io), 58 I/O40 2B4 (io), 59 I/O41 2B3 (io), 60 I/O42 2B2 (io), 61 I2/CLK2 (in), 62 VCC (power), 63 GND (power), 64 I3/CLK3 (in), 65 I/O43 3B2 (io), 66 I/O44 3B3 (io), 67 I/O45 3B4 (io), 68 I/O46 3B7 (io), 69 I/O47 3B8 (io), 70 I/O48 3B11 (io), 71 I/O49 3B12 (io), 72 I/O50 3B13 (io), 73 I/O51 3A12 (io), 74 TDO (out), 75 GND (power), 76 GND (power), 77 I/O52 3A7 (io), 78 I/O53 3A6 (io), 79 I/O54 3A5 (io), 80 I/O55 3A4 (io), 81 I/O56 3A3 (io), 82 I/O57 3A2 (io), 83 I/O58 3A1 (io), 84 I/O59 3A0 (io), 85 NC, 86 VCC (power), 87 GND (power), 88 GND (power), 89 VCC (power), 90 I/O60 0A0 (io), 91 I/O61 0A1 (io), 92 I/O62 0A2 (io), 93 I/O63 0A3 (io), 94 I/O64 0A4 (io), 95 I/O65 0A5 (io), 96 I/O66 0A6 (io), 97 I/O67 0A7 (io), 98 NC, 99 GND (power), 100 GND (power)

## M5LV-256/68-15YI
designator U?
High-Density and High-I/O Complex PLD
footprint PQFP100_N (QFP, 100-Leads, Body 20x14mm, Pitch 0.65mm, IPC Medium Density)
footprint PQFP100_L (QFP, 100-Leads, Body 20x14mm, Pitch 0.65mm, IPC High Density)
footprint PQFP100_M (QFP, 100-Leads, Body 20x14mm, Pitch 0.65mm, IPC Low Density)
3D model PQFP-100 (100-Pin Quad Flat Pack Rectangular 0.65 mm Pitch)
pins: 1 GND (power), 2 GND (power), 3 TDI (in), 4 I/O0 0A12 (io), 5 I/O1 0B13 (io), 6 I/O2 0B12 (io), 7 I/O3 0B11 (io), 8 I/O4 0B8 (io), 9 I/O5 0B7 (io), 10 I/O6 0B4 (io), 11 I/O7 0B3 (io), 12 I/O8 0B2 (io), 13 I0/CLK0 (in), 14 VCC (power), 15 VCC (power), 16 GND (power), 17 GND (power), 18 I1/CLK1 (in), 19 I/O9 1B2 (io), 20 I/O10 1B3 (io), 21 I/O11 1B4 (io), 22 I/O12 1B7 (io), 23 I/O13 1B8 (io), 24 I/O14 1B11 (io), 25 I/O15 1B12 (io), 26 I/O16 1B13 (io), 27 I/O17 1A12 (io), 28 TCK (in), 29 GND (power), 30 GND (power), 31 I/O18 1A7 (io), 32 I/O19 1A6 (io), 33 I/O20 1A5 (io), 34 I/O21 1A4 (io), 35 I/O22 1A3 (io), 36 I/O23 1A2 (io), 37 I/O24 1A1 (io), 38 I/O25 1A0 (io), 39 VCC (power), 40 GND (power), 41 GND (power), 42 VCC (power), 43 I/O26 2A0 (io), 44 I/O27 2A1 (io), 45 I/O28 2A2 (io), 46 I/O29 2A3 (io), 47 I/O30 2A4 (io), 48 I/O31 2A5 (io), 49 I/O32 2A6 (io), 50 I/O33 2A7 (io), 51 GND (power), 52 GND (power), 53 TMS (in), 54 I/O34 2A12 (io), 55 I/O35 2B13 (io), 56 I/O36 2B12 (io), 57 I/O37 2B11 (io), 58 I/O38 2B8 (io), 59 I/O39 2B7 (io), 60 I/O40 2B4 (io), 61 I/O41 2B3 (io), 62 I/O42 2B2 (io), 63 I2/CLK2 (in), 64 VCC (power), 65 VCC (power), 66 GND (power), 67 GND (power), 68 I3/CLK3 (in), 69 I/O43 3B2 (io), 70 I/O44 3B3 (io), 71 I/O45 3B4 (io), 72 I/O46 3B7 (io), 73 I/O47 3B8 (io), 74 I/O48 3B11 (io), 75 I/O49 3B12 (io), 76 I/O50 3B13 (io), 77 I/O51 3A12 (io), 78 TDO (out), 79 GND (power), 80 GND (power), 81 I/O52 3A7 (io), 82 I/O53 3A6 (io), 83 I/O54 3A5 (io), 84 I/O55 3A4 (io), 85 I/O56 3A3 (io), 86 I/O57 3A2 (io), 87 I/O58 3A1 (io), 88 I/O59 3A0 (io), 89 VCC (power), 90 GND (power), 91 GND (power), 92 VCC (power), 93 I/O60 0A0 (io), 94 I/O61 0A1 (io), 95 I/O62 0A2 (io), 96 I/O63 0A3 (io), 97 I/O64 0A4 (io), 98 I/O65 0A5 (io), 99 I/O66 0A6 (io), 100 I/O67 0A7 (io)

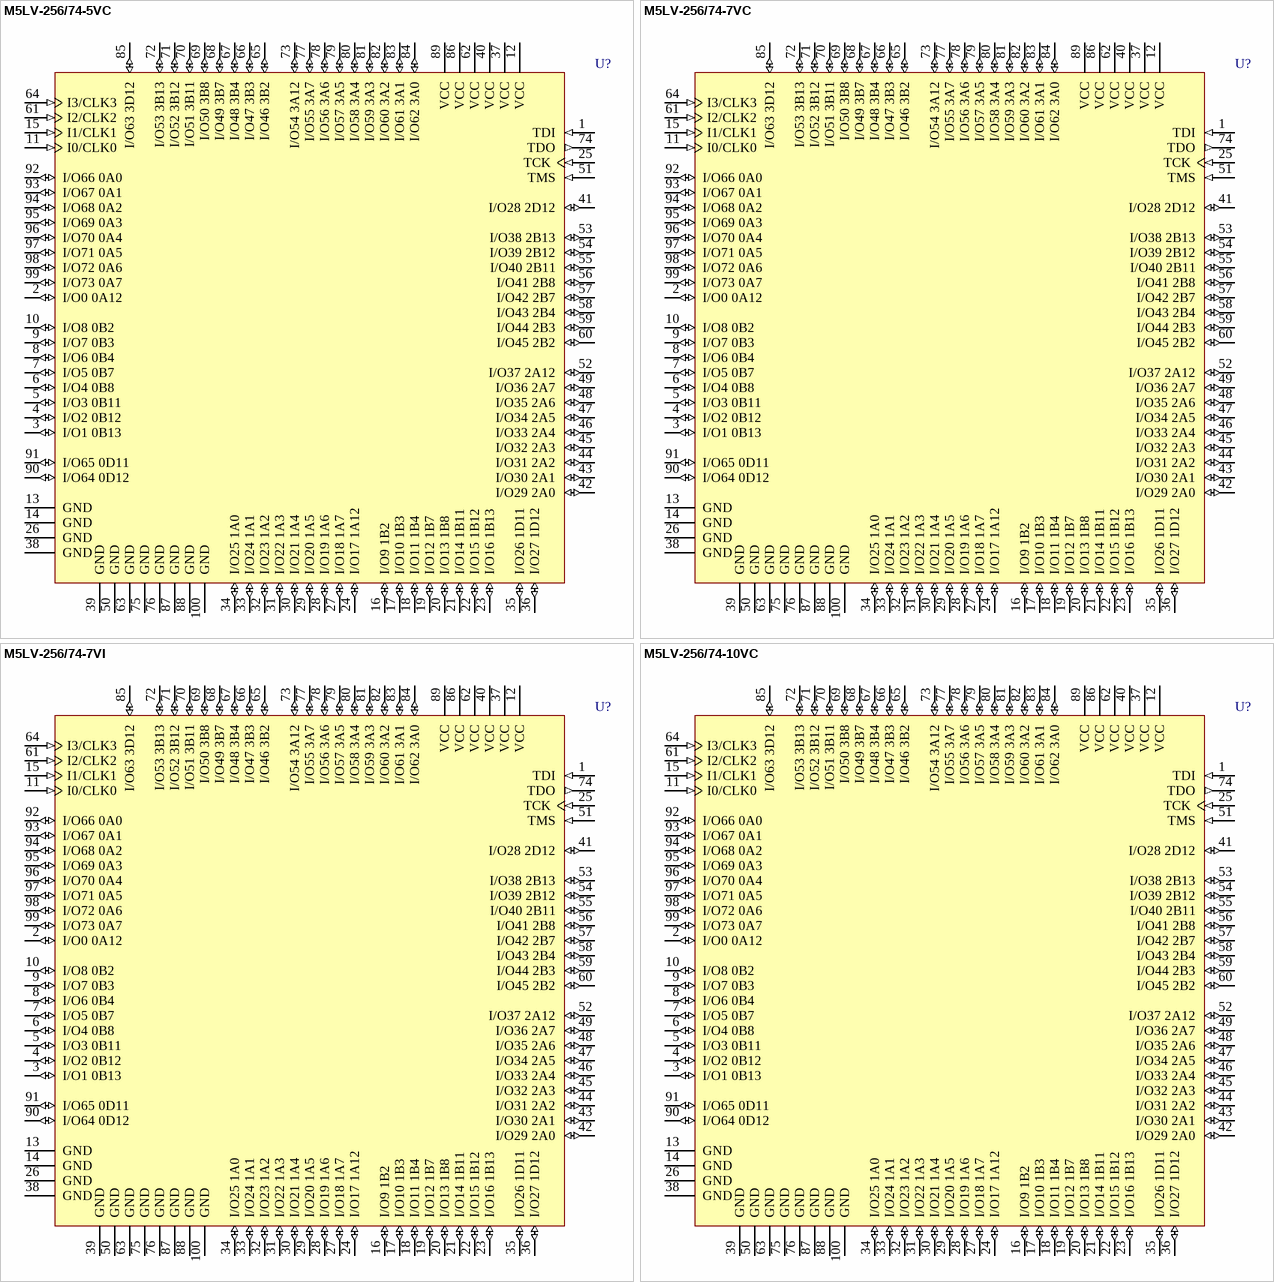
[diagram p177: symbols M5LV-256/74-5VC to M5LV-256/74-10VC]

## M5LV-256/74-5VC
designator U?
High-Density and High-I/O Complex PLD
footprint TQFP100_N (Thin QFP, 100-Leads, Body 14x14mm, Pitch 0.5mm, IPC Medium Density)
footprint TQFP100_L (Thin QFP, 100-Leads, Body 14x14mm, Pitch 0.5mm, IPC High Density)
footprint TQFP100_M (Thin QFP, 100-Leads, Body 14x14mm, Pitch 0.5mm, IPC Low Density)
3D model M5LV-TQFP100 (100-Pin Thin Quad Flat Pack (TQFP100))
pins: 1 TDI (in), 2 I/O0 0A12 (io), 3 I/O1 0B13 (io), 4 I/O2 0B12 (io), 5 I/O3 0B11 (io), 6 I/O4 0B8 (io), 7 I/O5 0B7 (io), 8 I/O6 0B4 (io), 9 I/O7 0B3 (io), 10 I/O8 0B2 (io), 11 I0/CLK0 (in), 12 VCC (power), 13 GND (power), 14 GND (power), 15 I1/CLK1 (in), 16 I/O9 1B2 (io), 17 I/O10 1B3 (io), 18 I/O11 1B4 (io), 19 I/O12 1B7 (io), 20 I/O13 1B8 (io), 21 I/O14 1B11 (io), 22 I/O15 1B12 (io), 23 I/O16 1B13 (io), 24 I/O17 1A12 (io), 25 TCK (in), 26 GND (power), 27 I/O18 1A7 (io), 28 I/O19 1A6 (io), 29 I/O20 1A5 (io), 30 I/O21 1A4 (io), 31 I/O22 1A3 (io), 32 I/O23 1A2 (io), 33 I/O24 1A1 (io), 34 I/O25 1A0 (io), 35 I/O26 1D11 (io), 36 I/O27 1D12 (io), 37 VCC (power), 38 GND (power), 39 GND (power), 40 VCC (power), 41 I/O28 2D12 (io), 42 I/O29 2A0 (io), 43 I/O30 2A1 (io), 44 I/O31 2A2 (io), 45 I/O32 2A3 (io), 46 I/O33 2A4 (io), 47 I/O34 2A5 (io), 48 I/O35 2A6 (io), 49 I/O36 2A7 (io), 50 GND (power), 51 TMS (in), 52 I/O37 2A12 (io), 53 I/O38 2B13 (io), 54 I/O39 2B12 (io), 55 I/O40 2B11 (io), 56 I/O41 2B8 (io), 57 I/O42 2B7 (io), 58 I/O43 2B4 (io), 59 I/O44 2B3 (io), 60 I/O45 2B2 (io), 61 I2/CLK2 (in), 62 VCC (power), 63 GND (power), 64 I3/CLK3 (in), 65 I/O46 3B2 (io), 66 I/O47 3B3 (io), 67 I/O48 3B4 (io), 68 I/O49 3B7 (io), 69 I/O50 3B8 (io), 70 I/O51 3B11 (io), 71 I/O52 3B12 (io), 72 I/O53 3B13 (io), 73 I/O54 3A12 (io), 74 TDO (out), 75 GND (power), 76 GND (power), 77 I/O55 3A7 (io), 78 I/O56 3A6 (io), 79 I/O57 3A5 (io), 80 I/O58 3A4 (io), 81 I/O59 3A3 (io), 82 I/O60 3A2 (io), 83 I/O61 3A1 (io), 84 I/O62 3A0 (io), 85 I/O63 3D12 (io), 86 VCC (power), 87 GND (power), 88 GND (power), 89 VCC (power), 90 I/O64 0D12 (io), 91 I/O65 0D11 (io), 92 I/O66 0A0 (io), 93 I/O67 0A1 (io), 94 I/O68 0A2 (io), 95 I/O69 0A3 (io), 96 I/O70 0A4 (io), 97 I/O71 0A5 (io), 98 I/O72 0A6 (io), 99 I/O73 0A7 (io), 100 GND (power)

## M5LV-256/74-7VC
designator U?
High-Density and High-I/O Complex PLD
footprint TQFP100_N (Thin QFP, 100-Leads, Body 14x14mm, Pitch 0.5mm, IPC Medium Density)
footprint TQFP100_L (Thin QFP, 100-Leads, Body 14x14mm, Pitch 0.5mm, IPC High Density)
footprint TQFP100_M (Thin QFP, 100-Leads, Body 14x14mm, Pitch 0.5mm, IPC Low Density)
3D model M5LV-TQFP100 (100-Pin Thin Quad Flat Pack (TQFP100))
pins: 1 TDI (in), 2 I/O0 0A12 (io), 3 I/O1 0B13 (io), 4 I/O2 0B12 (io), 5 I/O3 0B11 (io), 6 I/O4 0B8 (io), 7 I/O5 0B7 (io), 8 I/O6 0B4 (io), 9 I/O7 0B3 (io), 10 I/O8 0B2 (io), 11 I0/CLK0 (in), 12 VCC (power), 13 GND (power), 14 GND (power), 15 I1/CLK1 (in), 16 I/O9 1B2 (io), 17 I/O10 1B3 (io), 18 I/O11 1B4 (io), 19 I/O12 1B7 (io), 20 I/O13 1B8 (io), 21 I/O14 1B11 (io), 22 I/O15 1B12 (io), 23 I/O16 1B13 (io), 24 I/O17 1A12 (io), 25 TCK (in), 26 GND (power), 27 I/O18 1A7 (io), 28 I/O19 1A6 (io), 29 I/O20 1A5 (io), 30 I/O21 1A4 (io), 31 I/O22 1A3 (io), 32 I/O23 1A2 (io), 33 I/O24 1A1 (io), 34 I/O25 1A0 (io), 35 I/O26 1D11 (io), 36 I/O27 1D12 (io), 37 VCC (power), 38 GND (power), 39 GND (power), 40 VCC (power), 41 I/O28 2D12 (io), 42 I/O29 2A0 (io), 43 I/O30 2A1 (io), 44 I/O31 2A2 (io), 45 I/O32 2A3 (io), 46 I/O33 2A4 (io), 47 I/O34 2A5 (io), 48 I/O35 2A6 (io), 49 I/O36 2A7 (io), 50 GND (power), 51 TMS (in), 52 I/O37 2A12 (io), 53 I/O38 2B13 (io), 54 I/O39 2B12 (io), 55 I/O40 2B11 (io), 56 I/O41 2B8 (io), 57 I/O42 2B7 (io), 58 I/O43 2B4 (io), 59 I/O44 2B3 (io), 60 I/O45 2B2 (io), 61 I2/CLK2 (in), 62 VCC (power), 63 GND (power), 64 I3/CLK3 (in), 65 I/O46 3B2 (io), 66 I/O47 3B3 (io), 67 I/O48 3B4 (io), 68 I/O49 3B7 (io), 69 I/O50 3B8 (io), 70 I/O51 3B11 (io), 71 I/O52 3B12 (io), 72 I/O53 3B13 (io), 73 I/O54 3A12 (io), 74 TDO (out), 75 GND (power), 76 GND (power), 77 I/O55 3A7 (io), 78 I/O56 3A6 (io), 79 I/O57 3A5 (io), 80 I/O58 3A4 (io), 81 I/O59 3A3 (io), 82 I/O60 3A2 (io), 83 I/O61 3A1 (io), 84 I/O62 3A0 (io), 85 I/O63 3D12 (io), 86 VCC (power), 87 GND (power), 88 GND (power), 89 VCC (power), 90 I/O64 0D12 (io), 91 I/O65 0D11 (io), 92 I/O66 0A0 (io), 93 I/O67 0A1 (io), 94 I/O68 0A2 (io), 95 I/O69 0A3 (io), 96 I/O70 0A4 (io), 97 I/O71 0A5 (io), 98 I/O72 0A6 (io), 99 I/O73 0A7 (io), 100 GND (power)

## M5LV-256/74-7VI
designator U?
High-Density and High-I/O Complex PLD
footprint TQFP100_N (Thin QFP, 100-Leads, Body 14x14mm, Pitch 0.5mm, IPC Medium Density)
footprint TQFP100_L (Thin QFP, 100-Leads, Body 14x14mm, Pitch 0.5mm, IPC High Density)
footprint TQFP100_M (Thin QFP, 100-Leads, Body 14x14mm, Pitch 0.5mm, IPC Low Density)
3D model M5LV-TQFP100 (100-Pin Thin Quad Flat Pack (TQFP100))
pins: 1 TDI (in), 2 I/O0 0A12 (io), 3 I/O1 0B13 (io), 4 I/O2 0B12 (io), 5 I/O3 0B11 (io), 6 I/O4 0B8 (io), 7 I/O5 0B7 (io), 8 I/O6 0B4 (io), 9 I/O7 0B3 (io), 10 I/O8 0B2 (io), 11 I0/CLK0 (in), 12 VCC (power), 13 GND (power), 14 GND (power), 15 I1/CLK1 (in), 16 I/O9 1B2 (io), 17 I/O10 1B3 (io), 18 I/O11 1B4 (io), 19 I/O12 1B7 (io), 20 I/O13 1B8 (io), 21 I/O14 1B11 (io), 22 I/O15 1B12 (io), 23 I/O16 1B13 (io), 24 I/O17 1A12 (io), 25 TCK (in), 26 GND (power), 27 I/O18 1A7 (io), 28 I/O19 1A6 (io), 29 I/O20 1A5 (io), 30 I/O21 1A4 (io), 31 I/O22 1A3 (io), 32 I/O23 1A2 (io), 33 I/O24 1A1 (io), 34 I/O25 1A0 (io), 35 I/O26 1D11 (io), 36 I/O27 1D12 (io), 37 VCC (power), 38 GND (power), 39 GND (power), 40 VCC (power), 41 I/O28 2D12 (io), 42 I/O29 2A0 (io), 43 I/O30 2A1 (io), 44 I/O31 2A2 (io), 45 I/O32 2A3 (io), 46 I/O33 2A4 (io), 47 I/O34 2A5 (io), 48 I/O35 2A6 (io), 49 I/O36 2A7 (io), 50 GND (power), 51 TMS (in), 52 I/O37 2A12 (io), 53 I/O38 2B13 (io), 54 I/O39 2B12 (io), 55 I/O40 2B11 (io), 56 I/O41 2B8 (io), 57 I/O42 2B7 (io), 58 I/O43 2B4 (io), 59 I/O44 2B3 (io), 60 I/O45 2B2 (io), 61 I2/CLK2 (in), 62 VCC (power), 63 GND (power), 64 I3/CLK3 (in), 65 I/O46 3B2 (io), 66 I/O47 3B3 (io), 67 I/O48 3B4 (io), 68 I/O49 3B7 (io), 69 I/O50 3B8 (io), 70 I/O51 3B11 (io), 71 I/O52 3B12 (io), 72 I/O53 3B13 (io), 73 I/O54 3A12 (io), 74 TDO (out), 75 GND (power), 76 GND (power), 77 I/O55 3A7 (io), 78 I/O56 3A6 (io), 79 I/O57 3A5 (io), 80 I/O58 3A4 (io), 81 I/O59 3A3 (io), 82 I/O60 3A2 (io), 83 I/O61 3A1 (io), 84 I/O62 3A0 (io), 85 I/O63 3D12 (io), 86 VCC (power), 87 GND (power), 88 GND (power), 89 VCC (power), 90 I/O64 0D12 (io), 91 I/O65 0D11 (io), 92 I/O66 0A0 (io), 93 I/O67 0A1 (io), 94 I/O68 0A2 (io), 95 I/O69 0A3 (io), 96 I/O70 0A4 (io), 97 I/O71 0A5 (io), 98 I/O72 0A6 (io), 99 I/O73 0A7 (io), 100 GND (power)

## M5LV-256/74-10VC
designator U?
High-Density and High-I/O Complex PLD
footprint TQFP100_N (Thin QFP, 100-Leads, Body 14x14mm, Pitch 0.5mm, IPC Medium Density)
footprint TQFP100_L (Thin QFP, 100-Leads, Body 14x14mm, Pitch 0.5mm, IPC High Density)
footprint TQFP100_M (Thin QFP, 100-Leads, Body 14x14mm, Pitch 0.5mm, IPC Low Density)
3D model M5LV-TQFP100 (100-Pin Thin Quad Flat Pack (TQFP100))
pins: 1 TDI (in), 2 I/O0 0A12 (io), 3 I/O1 0B13 (io), 4 I/O2 0B12 (io), 5 I/O3 0B11 (io), 6 I/O4 0B8 (io), 7 I/O5 0B7 (io), 8 I/O6 0B4 (io), 9 I/O7 0B3 (io), 10 I/O8 0B2 (io), 11 I0/CLK0 (in), 12 VCC (power), 13 GND (power), 14 GND (power), 15 I1/CLK1 (in), 16 I/O9 1B2 (io), 17 I/O10 1B3 (io), 18 I/O11 1B4 (io), 19 I/O12 1B7 (io), 20 I/O13 1B8 (io), 21 I/O14 1B11 (io), 22 I/O15 1B12 (io), 23 I/O16 1B13 (io), 24 I/O17 1A12 (io), 25 TCK (in), 26 GND (power), 27 I/O18 1A7 (io), 28 I/O19 1A6 (io), 29 I/O20 1A5 (io), 30 I/O21 1A4 (io), 31 I/O22 1A3 (io), 32 I/O23 1A2 (io), 33 I/O24 1A1 (io), 34 I/O25 1A0 (io), 35 I/O26 1D11 (io), 36 I/O27 1D12 (io), 37 VCC (power), 38 GND (power), 39 GND (power), 40 VCC (power), 41 I/O28 2D12 (io), 42 I/O29 2A0 (io), 43 I/O30 2A1 (io), 44 I/O31 2A2 (io), 45 I/O32 2A3 (io), 46 I/O33 2A4 (io), 47 I/O34 2A5 (io), 48 I/O35 2A6 (io), 49 I/O36 2A7 (io), 50 GND (power), 51 TMS (in), 52 I/O37 2A12 (io), 53 I/O38 2B13 (io), 54 I/O39 2B12 (io), 55 I/O40 2B11 (io), 56 I/O41 2B8 (io), 57 I/O42 2B7 (io), 58 I/O43 2B4 (io), 59 I/O44 2B3 (io), 60 I/O45 2B2 (io), 61 I2/CLK2 (in), 62 VCC (power), 63 GND (power), 64 I3/CLK3 (in), 65 I/O46 3B2 (io), 66 I/O47 3B3 (io), 67 I/O48 3B4 (io), 68 I/O49 3B7 (io), 69 I/O50 3B8 (io), 70 I/O51 3B11 (io), 71 I/O52 3B12 (io), 72 I/O53 3B13 (io), 73 I/O54 3A12 (io), 74 TDO (out), 75 GND (power), 76 GND (power), 77 I/O55 3A7 (io), 78 I/O56 3A6 (io), 79 I/O57 3A5 (io), 80 I/O58 3A4 (io), 81 I/O59 3A3 (io), 82 I/O60 3A2 (io), 83 I/O61 3A1 (io), 84 I/O62 3A0 (io), 85 I/O63 3D12 (io), 86 VCC (power), 87 GND (power), 88 GND (power), 89 VCC (power), 90 I/O64 0D12 (io), 91 I/O65 0D11 (io), 92 I/O66 0A0 (io), 93 I/O67 0A1 (io), 94 I/O68 0A2 (io), 95 I/O69 0A3 (io), 96 I/O70 0A4 (io), 97 I/O71 0A5 (io), 98 I/O72 0A6 (io), 99 I/O73 0A7 (io), 100 GND (power)

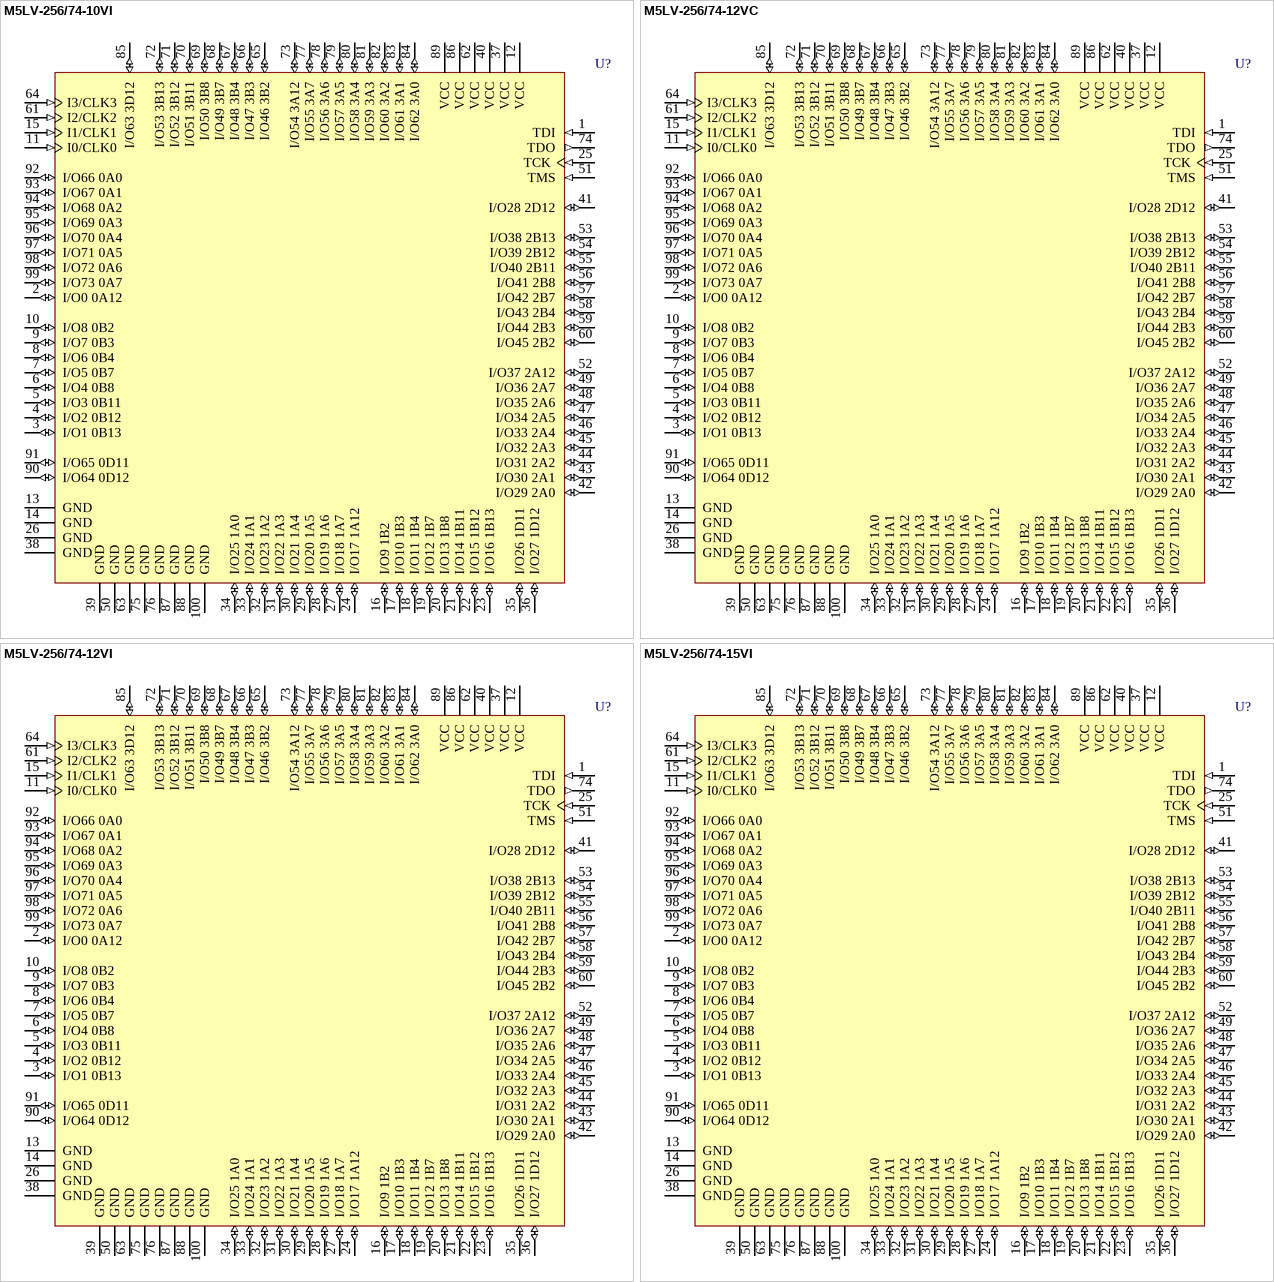
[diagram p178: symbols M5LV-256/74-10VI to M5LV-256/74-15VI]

## M5LV-256/74-10VI
designator U?
High-Density and High-I/O Complex PLD
footprint TQFP100_N (Thin QFP, 100-Leads, Body 14x14mm, Pitch 0.5mm, IPC Medium Density)
footprint TQFP100_L (Thin QFP, 100-Leads, Body 14x14mm, Pitch 0.5mm, IPC High Density)
footprint TQFP100_M (Thin QFP, 100-Leads, Body 14x14mm, Pitch 0.5mm, IPC Low Density)
3D model M5LV-TQFP100 (100-Pin Thin Quad Flat Pack (TQFP100))
pins: 1 TDI (in), 2 I/O0 0A12 (io), 3 I/O1 0B13 (io), 4 I/O2 0B12 (io), 5 I/O3 0B11 (io), 6 I/O4 0B8 (io), 7 I/O5 0B7 (io), 8 I/O6 0B4 (io), 9 I/O7 0B3 (io), 10 I/O8 0B2 (io), 11 I0/CLK0 (in), 12 VCC (power), 13 GND (power), 14 GND (power), 15 I1/CLK1 (in), 16 I/O9 1B2 (io), 17 I/O10 1B3 (io), 18 I/O11 1B4 (io), 19 I/O12 1B7 (io), 20 I/O13 1B8 (io), 21 I/O14 1B11 (io), 22 I/O15 1B12 (io), 23 I/O16 1B13 (io), 24 I/O17 1A12 (io), 25 TCK (in), 26 GND (power), 27 I/O18 1A7 (io), 28 I/O19 1A6 (io), 29 I/O20 1A5 (io), 30 I/O21 1A4 (io), 31 I/O22 1A3 (io), 32 I/O23 1A2 (io), 33 I/O24 1A1 (io), 34 I/O25 1A0 (io), 35 I/O26 1D11 (io), 36 I/O27 1D12 (io), 37 VCC (power), 38 GND (power), 39 GND (power), 40 VCC (power), 41 I/O28 2D12 (io), 42 I/O29 2A0 (io), 43 I/O30 2A1 (io), 44 I/O31 2A2 (io), 45 I/O32 2A3 (io), 46 I/O33 2A4 (io), 47 I/O34 2A5 (io), 48 I/O35 2A6 (io), 49 I/O36 2A7 (io), 50 GND (power), 51 TMS (in), 52 I/O37 2A12 (io), 53 I/O38 2B13 (io), 54 I/O39 2B12 (io), 55 I/O40 2B11 (io), 56 I/O41 2B8 (io), 57 I/O42 2B7 (io), 58 I/O43 2B4 (io), 59 I/O44 2B3 (io), 60 I/O45 2B2 (io), 61 I2/CLK2 (in), 62 VCC (power), 63 GND (power), 64 I3/CLK3 (in), 65 I/O46 3B2 (io), 66 I/O47 3B3 (io), 67 I/O48 3B4 (io), 68 I/O49 3B7 (io), 69 I/O50 3B8 (io), 70 I/O51 3B11 (io), 71 I/O52 3B12 (io), 72 I/O53 3B13 (io), 73 I/O54 3A12 (io), 74 TDO (out), 75 GND (power), 76 GND (power), 77 I/O55 3A7 (io), 78 I/O56 3A6 (io), 79 I/O57 3A5 (io), 80 I/O58 3A4 (io), 81 I/O59 3A3 (io), 82 I/O60 3A2 (io), 83 I/O61 3A1 (io), 84 I/O62 3A0 (io), 85 I/O63 3D12 (io), 86 VCC (power), 87 GND (power), 88 GND (power), 89 VCC (power), 90 I/O64 0D12 (io), 91 I/O65 0D11 (io), 92 I/O66 0A0 (io), 93 I/O67 0A1 (io), 94 I/O68 0A2 (io), 95 I/O69 0A3 (io), 96 I/O70 0A4 (io), 97 I/O71 0A5 (io), 98 I/O72 0A6 (io), 99 I/O73 0A7 (io), 100 GND (power)

## M5LV-256/74-12VC
designator U?
High-Density and High-I/O Complex PLD
footprint TQFP100_N (Thin QFP, 100-Leads, Body 14x14mm, Pitch 0.5mm, IPC Medium Density)
footprint TQFP100_L (Thin QFP, 100-Leads, Body 14x14mm, Pitch 0.5mm, IPC High Density)
footprint TQFP100_M (Thin QFP, 100-Leads, Body 14x14mm, Pitch 0.5mm, IPC Low Density)
3D model M5LV-TQFP100 (100-Pin Thin Quad Flat Pack (TQFP100))
pins: 1 TDI (in), 2 I/O0 0A12 (io), 3 I/O1 0B13 (io), 4 I/O2 0B12 (io), 5 I/O3 0B11 (io), 6 I/O4 0B8 (io), 7 I/O5 0B7 (io), 8 I/O6 0B4 (io), 9 I/O7 0B3 (io), 10 I/O8 0B2 (io), 11 I0/CLK0 (in), 12 VCC (power), 13 GND (power), 14 GND (power), 15 I1/CLK1 (in), 16 I/O9 1B2 (io), 17 I/O10 1B3 (io), 18 I/O11 1B4 (io), 19 I/O12 1B7 (io), 20 I/O13 1B8 (io), 21 I/O14 1B11 (io), 22 I/O15 1B12 (io), 23 I/O16 1B13 (io), 24 I/O17 1A12 (io), 25 TCK (in), 26 GND (power), 27 I/O18 1A7 (io), 28 I/O19 1A6 (io), 29 I/O20 1A5 (io), 30 I/O21 1A4 (io), 31 I/O22 1A3 (io), 32 I/O23 1A2 (io), 33 I/O24 1A1 (io), 34 I/O25 1A0 (io), 35 I/O26 1D11 (io), 36 I/O27 1D12 (io), 37 VCC (power), 38 GND (power), 39 GND (power), 40 VCC (power), 41 I/O28 2D12 (io), 42 I/O29 2A0 (io), 43 I/O30 2A1 (io), 44 I/O31 2A2 (io), 45 I/O32 2A3 (io), 46 I/O33 2A4 (io), 47 I/O34 2A5 (io), 48 I/O35 2A6 (io), 49 I/O36 2A7 (io), 50 GND (power), 51 TMS (in), 52 I/O37 2A12 (io), 53 I/O38 2B13 (io), 54 I/O39 2B12 (io), 55 I/O40 2B11 (io), 56 I/O41 2B8 (io), 57 I/O42 2B7 (io), 58 I/O43 2B4 (io), 59 I/O44 2B3 (io), 60 I/O45 2B2 (io), 61 I2/CLK2 (in), 62 VCC (power), 63 GND (power), 64 I3/CLK3 (in), 65 I/O46 3B2 (io), 66 I/O47 3B3 (io), 67 I/O48 3B4 (io), 68 I/O49 3B7 (io), 69 I/O50 3B8 (io), 70 I/O51 3B11 (io), 71 I/O52 3B12 (io), 72 I/O53 3B13 (io), 73 I/O54 3A12 (io), 74 TDO (out), 75 GND (power), 76 GND (power), 77 I/O55 3A7 (io), 78 I/O56 3A6 (io), 79 I/O57 3A5 (io), 80 I/O58 3A4 (io), 81 I/O59 3A3 (io), 82 I/O60 3A2 (io), 83 I/O61 3A1 (io), 84 I/O62 3A0 (io), 85 I/O63 3D12 (io), 86 VCC (power), 87 GND (power), 88 GND (power), 89 VCC (power), 90 I/O64 0D12 (io), 91 I/O65 0D11 (io), 92 I/O66 0A0 (io), 93 I/O67 0A1 (io), 94 I/O68 0A2 (io), 95 I/O69 0A3 (io), 96 I/O70 0A4 (io), 97 I/O71 0A5 (io), 98 I/O72 0A6 (io), 99 I/O73 0A7 (io), 100 GND (power)

## M5LV-256/74-12VI
designator U?
High-Density and High-I/O Complex PLD
footprint TQFP100_N (Thin QFP, 100-Leads, Body 14x14mm, Pitch 0.5mm, IPC Medium Density)
footprint TQFP100_L (Thin QFP, 100-Leads, Body 14x14mm, Pitch 0.5mm, IPC High Density)
footprint TQFP100_M (Thin QFP, 100-Leads, Body 14x14mm, Pitch 0.5mm, IPC Low Density)
3D model M5LV-TQFP100 (100-Pin Thin Quad Flat Pack (TQFP100))
pins: 1 TDI (in), 2 I/O0 0A12 (io), 3 I/O1 0B13 (io), 4 I/O2 0B12 (io), 5 I/O3 0B11 (io), 6 I/O4 0B8 (io), 7 I/O5 0B7 (io), 8 I/O6 0B4 (io), 9 I/O7 0B3 (io), 10 I/O8 0B2 (io), 11 I0/CLK0 (in), 12 VCC (power), 13 GND (power), 14 GND (power), 15 I1/CLK1 (in), 16 I/O9 1B2 (io), 17 I/O10 1B3 (io), 18 I/O11 1B4 (io), 19 I/O12 1B7 (io), 20 I/O13 1B8 (io), 21 I/O14 1B11 (io), 22 I/O15 1B12 (io), 23 I/O16 1B13 (io), 24 I/O17 1A12 (io), 25 TCK (in), 26 GND (power), 27 I/O18 1A7 (io), 28 I/O19 1A6 (io), 29 I/O20 1A5 (io), 30 I/O21 1A4 (io), 31 I/O22 1A3 (io), 32 I/O23 1A2 (io), 33 I/O24 1A1 (io), 34 I/O25 1A0 (io), 35 I/O26 1D11 (io), 36 I/O27 1D12 (io), 37 VCC (power), 38 GND (power), 39 GND (power), 40 VCC (power), 41 I/O28 2D12 (io), 42 I/O29 2A0 (io), 43 I/O30 2A1 (io), 44 I/O31 2A2 (io), 45 I/O32 2A3 (io), 46 I/O33 2A4 (io), 47 I/O34 2A5 (io), 48 I/O35 2A6 (io), 49 I/O36 2A7 (io), 50 GND (power), 51 TMS (in), 52 I/O37 2A12 (io), 53 I/O38 2B13 (io), 54 I/O39 2B12 (io), 55 I/O40 2B11 (io), 56 I/O41 2B8 (io), 57 I/O42 2B7 (io), 58 I/O43 2B4 (io), 59 I/O44 2B3 (io), 60 I/O45 2B2 (io), 61 I2/CLK2 (in), 62 VCC (power), 63 GND (power), 64 I3/CLK3 (in), 65 I/O46 3B2 (io), 66 I/O47 3B3 (io), 67 I/O48 3B4 (io), 68 I/O49 3B7 (io), 69 I/O50 3B8 (io), 70 I/O51 3B11 (io), 71 I/O52 3B12 (io), 72 I/O53 3B13 (io), 73 I/O54 3A12 (io), 74 TDO (out), 75 GND (power), 76 GND (power), 77 I/O55 3A7 (io), 78 I/O56 3A6 (io), 79 I/O57 3A5 (io), 80 I/O58 3A4 (io), 81 I/O59 3A3 (io), 82 I/O60 3A2 (io), 83 I/O61 3A1 (io), 84 I/O62 3A0 (io), 85 I/O63 3D12 (io), 86 VCC (power), 87 GND (power), 88 GND (power), 89 VCC (power), 90 I/O64 0D12 (io), 91 I/O65 0D11 (io), 92 I/O66 0A0 (io), 93 I/O67 0A1 (io), 94 I/O68 0A2 (io), 95 I/O69 0A3 (io), 96 I/O70 0A4 (io), 97 I/O71 0A5 (io), 98 I/O72 0A6 (io), 99 I/O73 0A7 (io), 100 GND (power)

## M5LV-256/74-15VI
designator U?
High-Density and High-I/O Complex PLD
footprint TQFP100_N (Thin QFP, 100-Leads, Body 14x14mm, Pitch 0.5mm, IPC Medium Density)
footprint TQFP100_L (Thin QFP, 100-Leads, Body 14x14mm, Pitch 0.5mm, IPC High Density)
footprint TQFP100_M (Thin QFP, 100-Leads, Body 14x14mm, Pitch 0.5mm, IPC Low Density)
3D model M5LV-TQFP100 (100-Pin Thin Quad Flat Pack (TQFP100))
pins: 1 TDI (in), 2 I/O0 0A12 (io), 3 I/O1 0B13 (io), 4 I/O2 0B12 (io), 5 I/O3 0B11 (io), 6 I/O4 0B8 (io), 7 I/O5 0B7 (io), 8 I/O6 0B4 (io), 9 I/O7 0B3 (io), 10 I/O8 0B2 (io), 11 I0/CLK0 (in), 12 VCC (power), 13 GND (power), 14 GND (power), 15 I1/CLK1 (in), 16 I/O9 1B2 (io), 17 I/O10 1B3 (io), 18 I/O11 1B4 (io), 19 I/O12 1B7 (io), 20 I/O13 1B8 (io), 21 I/O14 1B11 (io), 22 I/O15 1B12 (io), 23 I/O16 1B13 (io), 24 I/O17 1A12 (io), 25 TCK (in), 26 GND (power), 27 I/O18 1A7 (io), 28 I/O19 1A6 (io), 29 I/O20 1A5 (io), 30 I/O21 1A4 (io), 31 I/O22 1A3 (io), 32 I/O23 1A2 (io), 33 I/O24 1A1 (io), 34 I/O25 1A0 (io), 35 I/O26 1D11 (io), 36 I/O27 1D12 (io), 37 VCC (power), 38 GND (power), 39 GND (power), 40 VCC (power), 41 I/O28 2D12 (io), 42 I/O29 2A0 (io), 43 I/O30 2A1 (io), 44 I/O31 2A2 (io), 45 I/O32 2A3 (io), 46 I/O33 2A4 (io), 47 I/O34 2A5 (io), 48 I/O35 2A6 (io), 49 I/O36 2A7 (io), 50 GND (power), 51 TMS (in), 52 I/O37 2A12 (io), 53 I/O38 2B13 (io), 54 I/O39 2B12 (io), 55 I/O40 2B11 (io), 56 I/O41 2B8 (io), 57 I/O42 2B7 (io), 58 I/O43 2B4 (io), 59 I/O44 2B3 (io), 60 I/O45 2B2 (io), 61 I2/CLK2 (in), 62 VCC (power), 63 GND (power), 64 I3/CLK3 (in), 65 I/O46 3B2 (io), 66 I/O47 3B3 (io), 67 I/O48 3B4 (io), 68 I/O49 3B7 (io), 69 I/O50 3B8 (io), 70 I/O51 3B11 (io), 71 I/O52 3B12 (io), 72 I/O53 3B13 (io), 73 I/O54 3A12 (io), 74 TDO (out), 75 GND (power), 76 GND (power), 77 I/O55 3A7 (io), 78 I/O56 3A6 (io), 79 I/O57 3A5 (io), 80 I/O58 3A4 (io), 81 I/O59 3A3 (io), 82 I/O60 3A2 (io), 83 I/O61 3A1 (io), 84 I/O62 3A0 (io), 85 I/O63 3D12 (io), 86 VCC (power), 87 GND (power), 88 GND (power), 89 VCC (power), 90 I/O64 0D12 (io), 91 I/O65 0D11 (io), 92 I/O66 0A0 (io), 93 I/O67 0A1 (io), 94 I/O68 0A2 (io), 95 I/O69 0A3 (io), 96 I/O70 0A4 (io), 97 I/O71 0A5 (io), 98 I/O72 0A6 (io), 99 I/O73 0A7 (io), 100 GND (power)

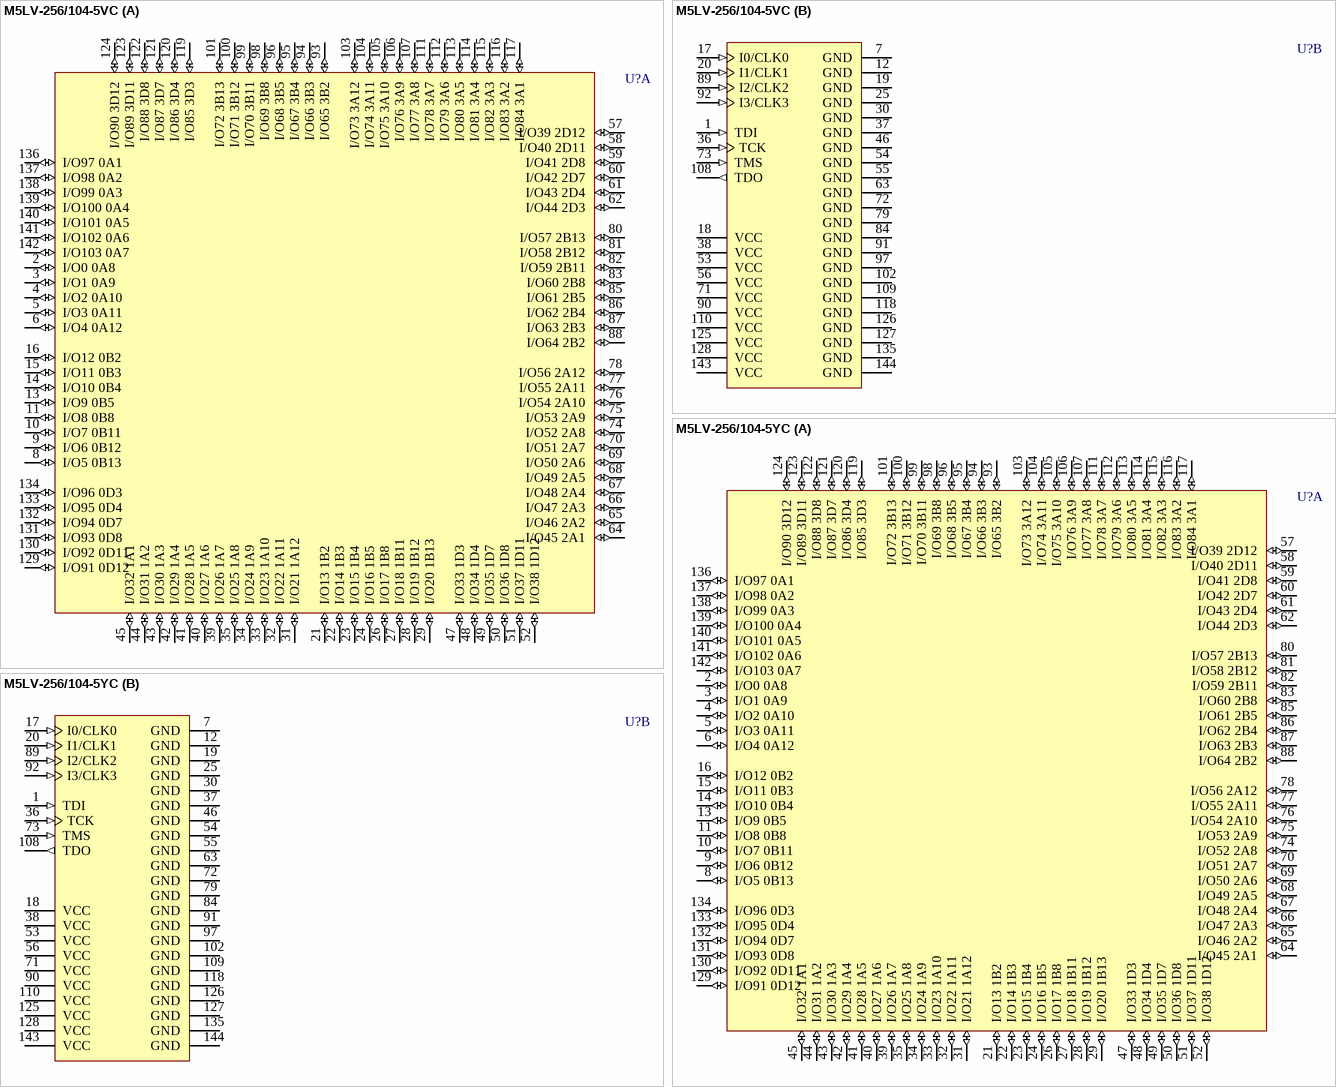
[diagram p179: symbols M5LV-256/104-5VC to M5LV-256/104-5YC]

## M5LV-256/104-5VC
designator U?
High-Density and High-I/O Complex PLD
footprint TQFP144_N (Thin QFP, 144-Leads, Body 20x20mm, Pitch 0.5mm, IPC Medium Density)
footprint TQFP144_L (Thin QFP, 144-Leads, Body 20x20mm, Pitch 0.5mm, IPC High Density)
footprint TQFP144_M (Thin QFP, 144-Leads, Body 20x20mm, Pitch 0.5mm, IPC Low Density)
3D model M5LV-TQFP144 (144-Pin Thin Quad Flat Pack (TQFP144))
part A pins: 2 I/O0 0A8 (io), 3 I/O1 0A9 (io), 4 I/O2 0A10 (io), 5 I/O3 0A11 (io), 6 I/O4 0A12 (io), 8 I/O5 0B13 (io), 9 I/O6 0B12 (io), 10 I/O7 0B11 (io), 11 I/O8 0B8 (io), 13 I/O9 0B5 (io), 14 I/O10 0B4 (io), 15 I/O11 0B3 (io), 16 I/O12 0B2 (io), 21 I/O13 1B2 (io), 22 I/O14 1B3 (io), 23 I/O15 1B4 (io), 24 I/O16 1B5 (io), 26 I/O17 1B8 (io), 27 I/O18 1B11 (io), 28 I/O19 1B12 (io), 29 I/O20 1B13 (io), 31 I/O21 1A12 (io), 32 I/O22 1A11 (io), 33 I/O23 1A10 (io), 34 I/O24 1A9 (io), 35 I/O25 1A8 (io), 39 I/O26 1A7 (io), 40 I/O27 1A6 (io), 41 I/O28 1A5 (io), 42 I/O29 1A4 (io), 43 I/O30 1A3 (io), 44 I/O31 1A2 (io), 45 I/O32 1A1 (io), 47 I/O33 1D3 (io), 48 I/O34 1D4 (io), 49 I/O35 1D7 (io), 50 I/O36 1D8 (io), 51 I/O37 1D11 (io), 52 I/O38 1D12 (io), 57 I/O39 2D12 (io), 58 I/O40 2D11 (io), 59 I/O41 2D8 (io), 60 I/O42 2D7 (io), 61 I/O43 2D4 (io), 62 I/O44 2D3 (io), 64 I/O45 2A1 (io), 65 I/O46 2A2 (io), 66 I/O47 2A3 (io), 67 I/O48 2A4 (io), 68 I/O49 2A5 (io), 69 I/O50 2A6 (io), 70 I/O51 2A7 (io), 74 I/O52 2A8 (io), 75 I/O53 2A9 (io), 76 I/O54 2A10 (io), 77 I/O55 2A11 (io), 78 I/O56 2A12 (io), 80 I/O57 2B13 (io), 81 I/O58 2B12 (io), 82 I/O59 2B11 (io), 83 I/O60 2B8 (io), 85 I/O61 2B5 (io), 86 I/O62 2B4 (io), 87 I/O63 2B3 (io), 88 I/O64 2B2 (io), 93 I/O65 3B2 (io), 94 I/O66 3B3 (io), 95 I/O67 3B4 (io), 96 I/O68 3B5 (io), 98 I/O69 3B8 (io), 99 I/O70 3B11 (io), 100 I/O71 3B12 (io), 101 I/O72 3B13 (io), 103 I/O73 3A12 (io), 104 I/O74 3A11 (io), 105 I/O75 3A10 (io), 106 I/O76 3A9 (io), 107 I/O77 3A8 (io), 111 I/O78 3A7 (io), 112 I/O79 3A6 (io), 113 I/O80 3A5 (io), 114 I/O81 3A4 (io), 115 I/O82 3A3 (io), 116 I/O83 3A2 (io), 117 I/O84 3A1 (io), 119 I/O85 3D3 (io), 120 I/O86 3D4 (io), 121 I/O87 3D7 (io), 122 I/O88 3D8 (io), 123 I/O89 3D11 (io), 124 I/O90 3D12 (io), 129 I/O91 0D12 (io), 130 I/O92 0D11 (io), 131 I/O93 0D8 (io), 132 I/O94 0D7 (io), 133 I/O95 0D4 (io), 134 I/O96 0D3 (io), 136 I/O97 0A1 (io), 137 I/O98 0A2 (io), 138 I/O99 0A3 (io), 139 I/O100 0A4 (io), 140 I/O101 0A5 (io), 141 I/O102 0A6 (io), 142 I/O103 0A7 (io)
part B pins: 1 TDI (in), 7 GND (power), 12 GND (power), 17 I0/CLK0 (in), 18 VCC (power), 19 GND (power), 20 I1/CLK1 (in), 25 GND (power), 30 GND (power), 36 TCK (in), 37 GND (power), 38 VCC (power), 46 GND (power), 53 VCC (power), 54 GND (power), 55 GND (power), 56 VCC (power), 63 GND (power), 71 VCC (power), 72 GND (power), 73 TMS (in), 79 GND (power), 84 GND (power), 89 I2/CLK2 (in), 90 VCC (power), 91 GND (power), 92 I3/CLK3 (in), 97 GND (power), 102 GND (power), 108 TDO (out), 109 GND (power), 110 VCC (power), 118 GND (power), 125 VCC (power), 126 GND (power), 127 GND (power), 128 VCC (power), 135 GND (power), 143 VCC (power), 144 GND (power)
